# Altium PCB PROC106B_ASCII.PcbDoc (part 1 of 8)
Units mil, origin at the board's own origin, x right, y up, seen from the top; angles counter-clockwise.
Board outline 4498.18 x 1060.53 mil, 8 copper layers (Top Layer, GND1, Sig1, PWR1, PWR2, Sig2, GND2, Bottom Layer), stack 69.602 mil thick; 439 components, 327 nets, 1548 pads, 843 vias.
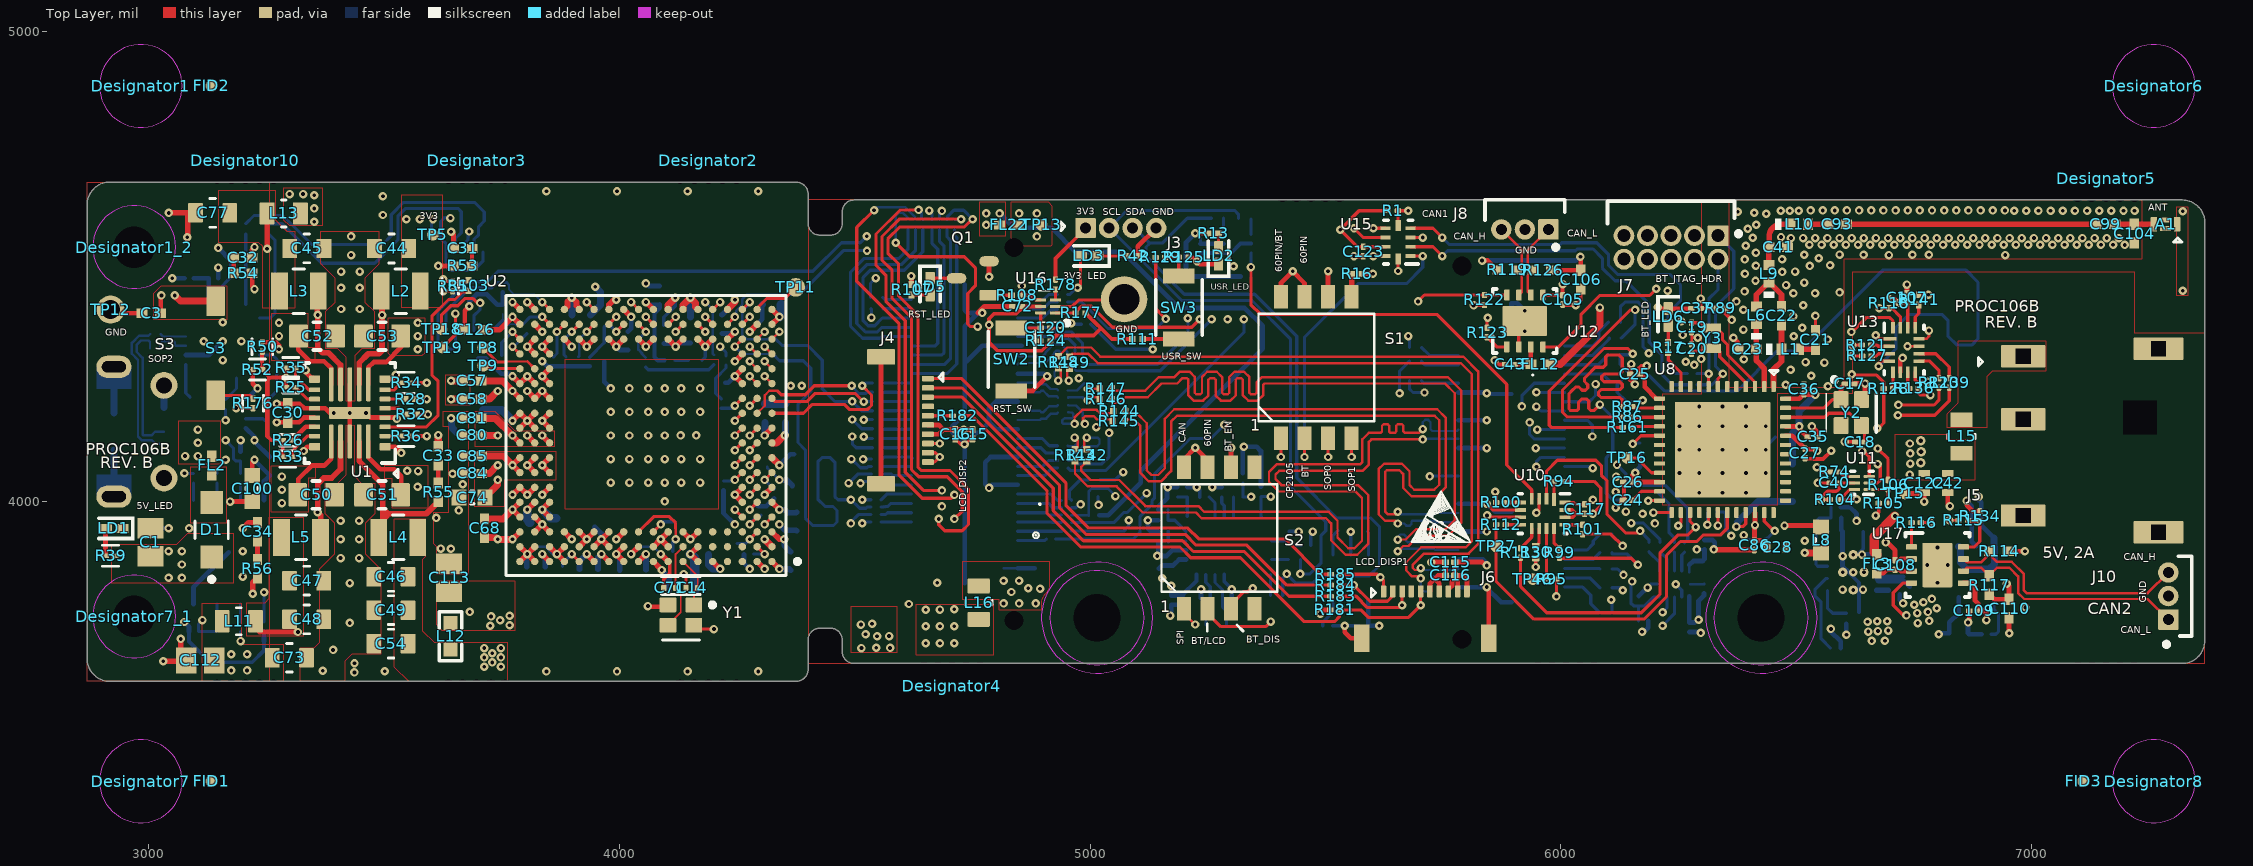
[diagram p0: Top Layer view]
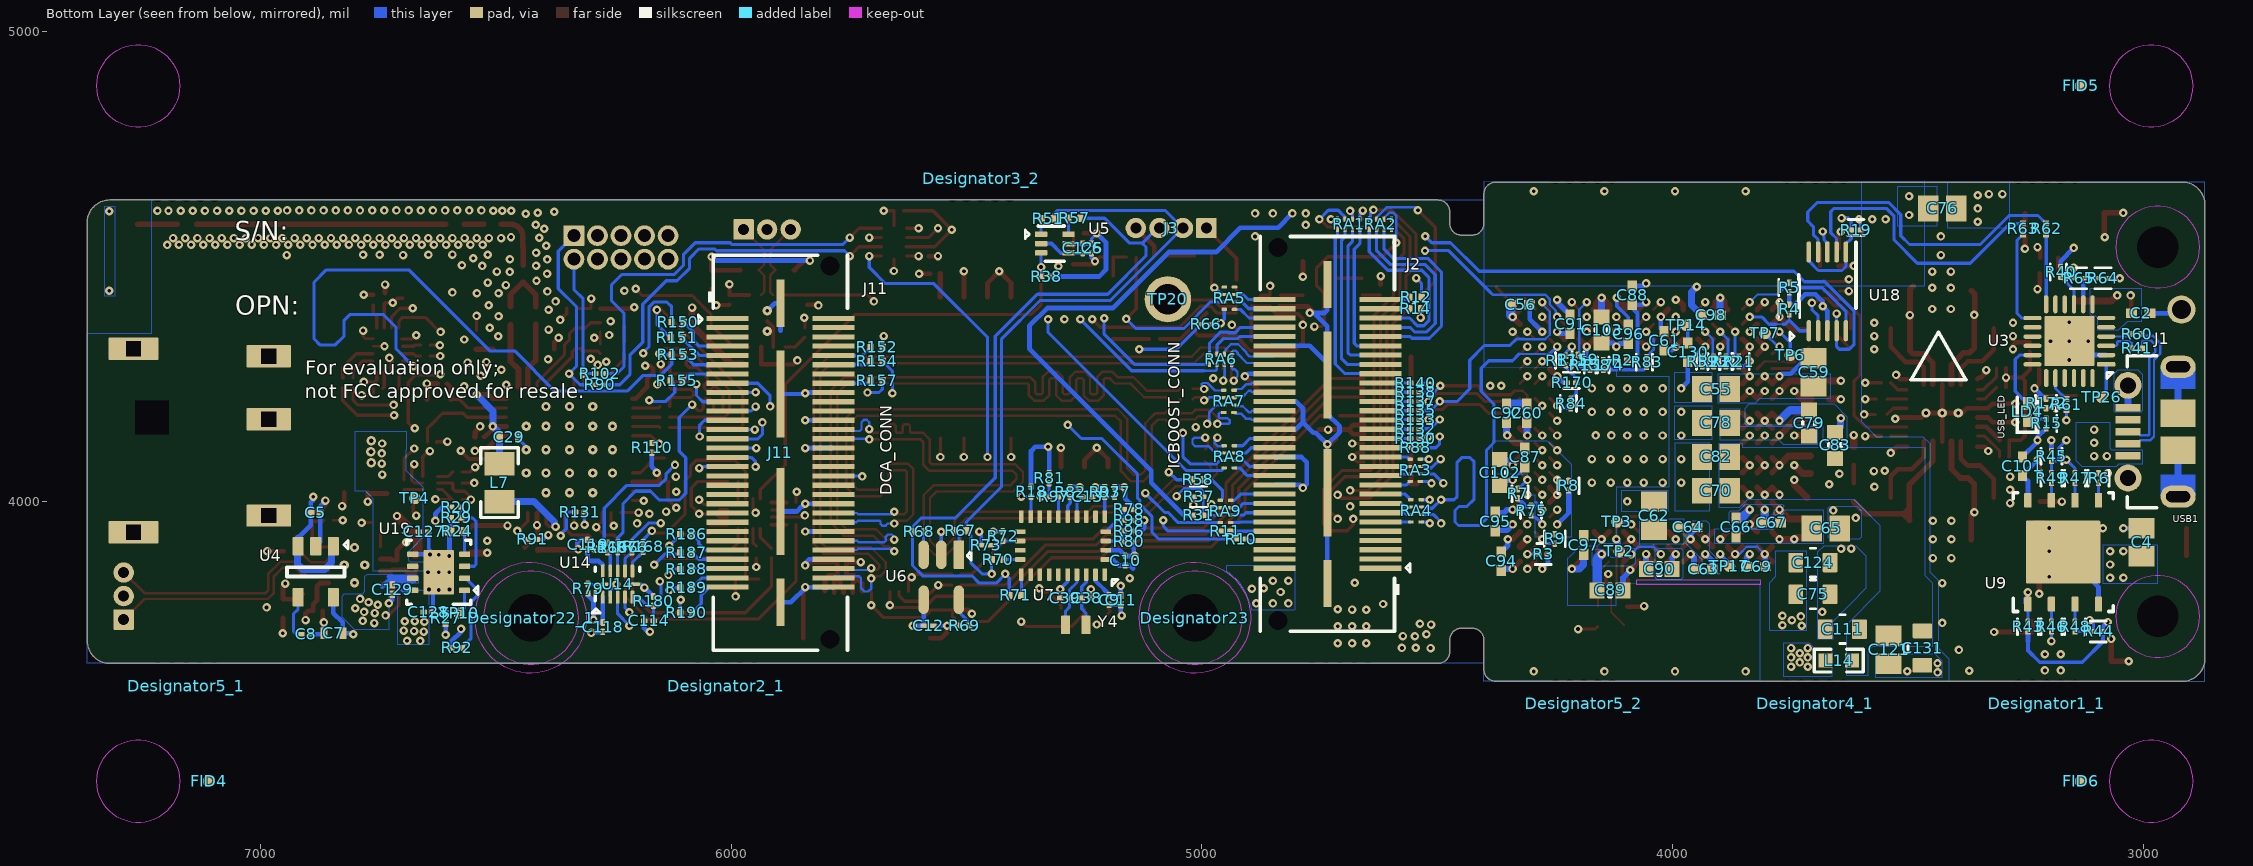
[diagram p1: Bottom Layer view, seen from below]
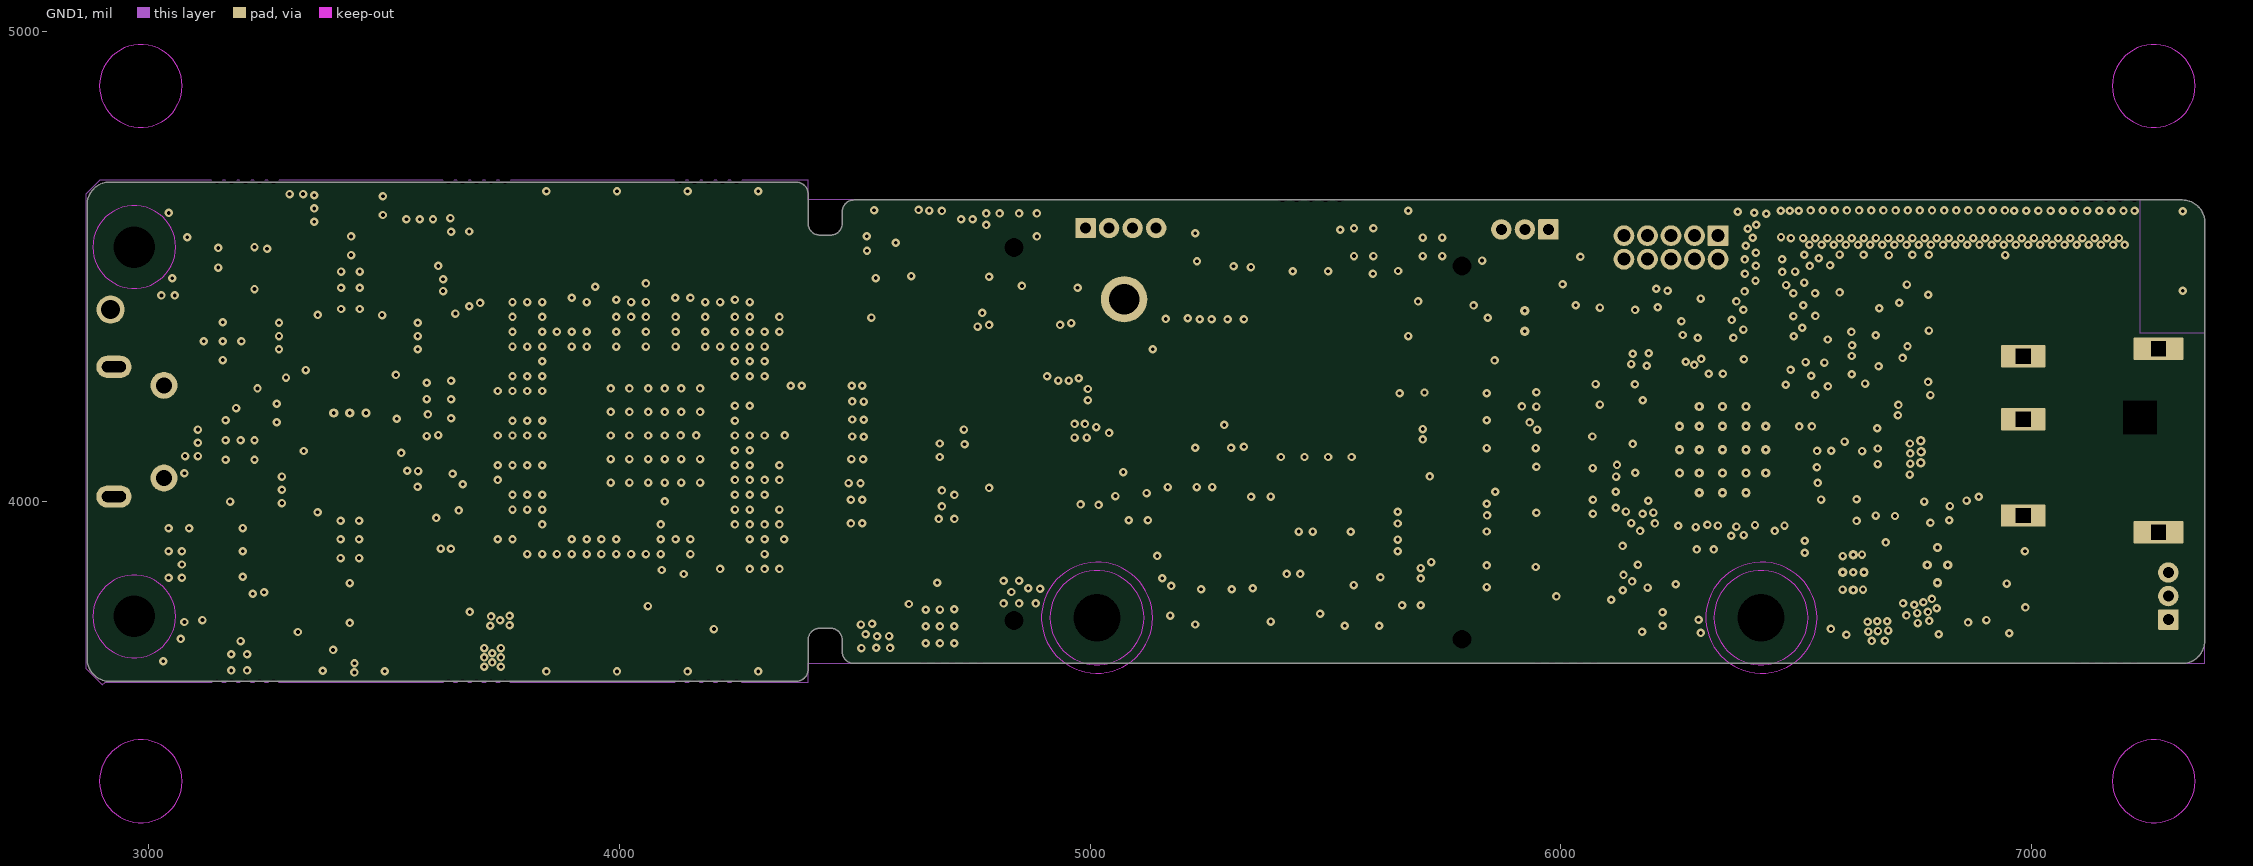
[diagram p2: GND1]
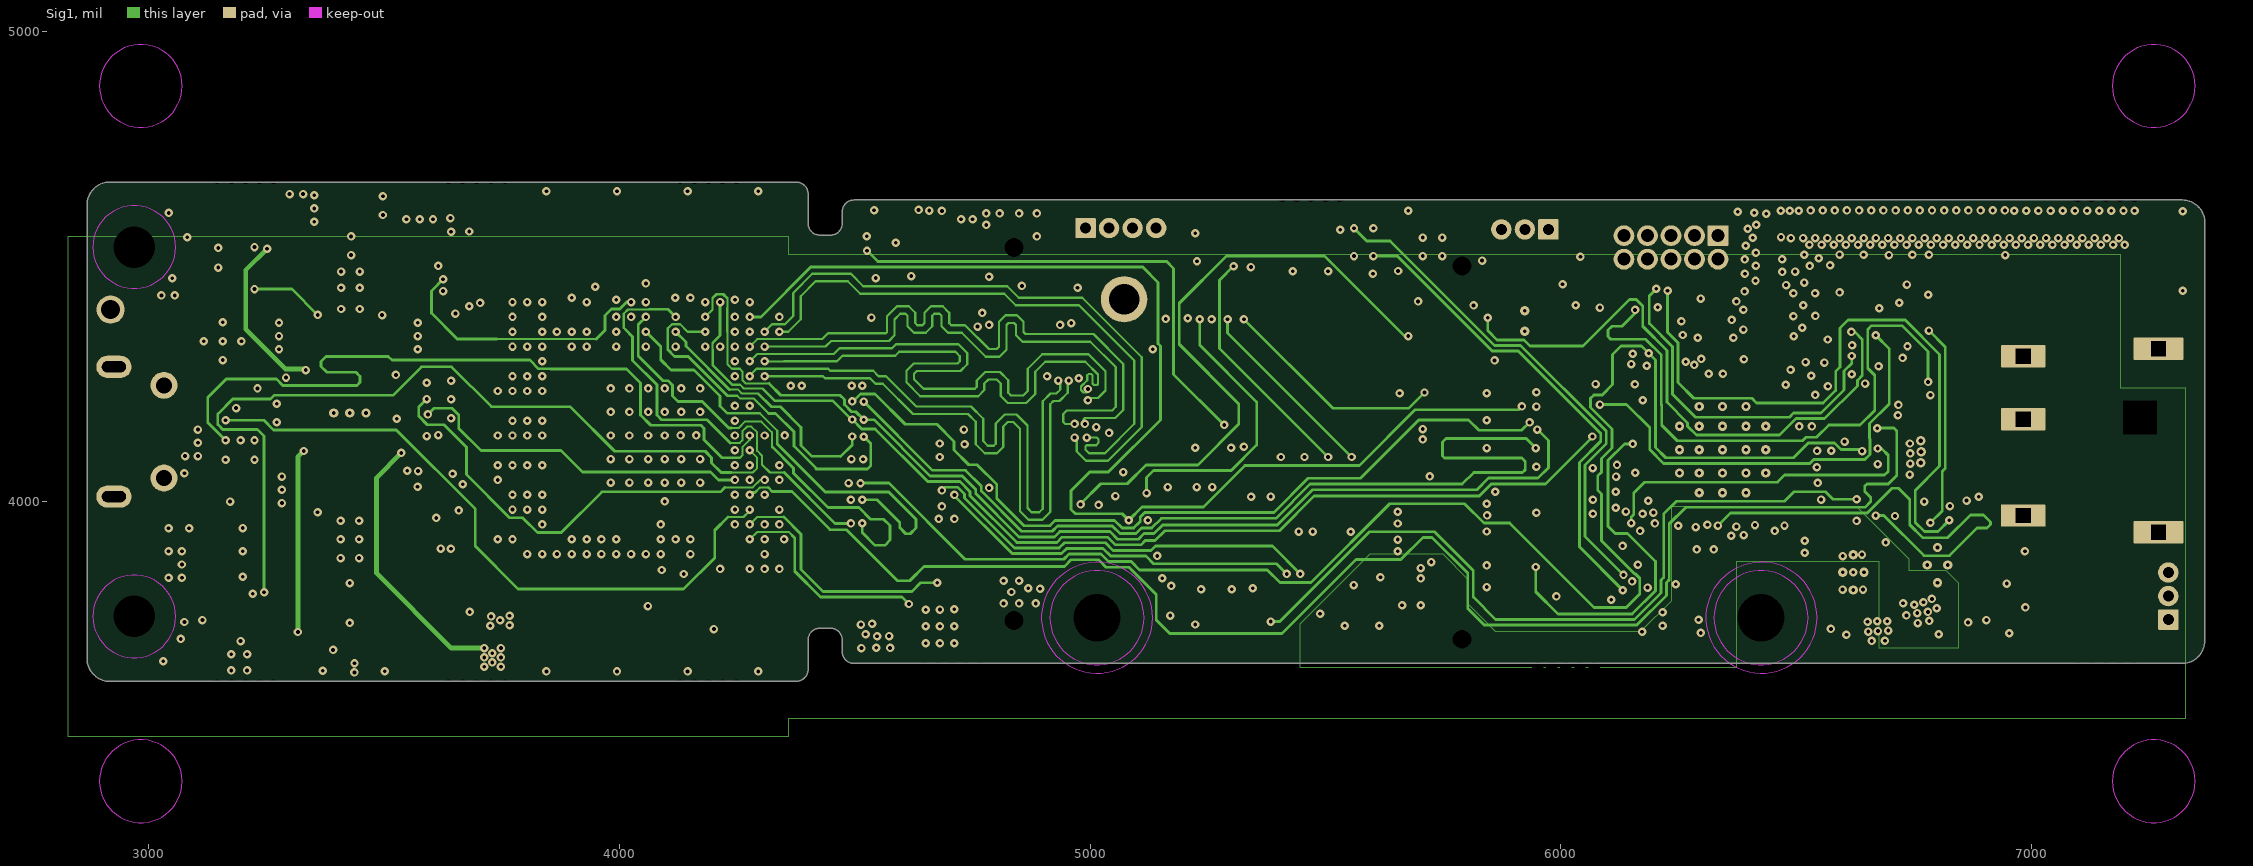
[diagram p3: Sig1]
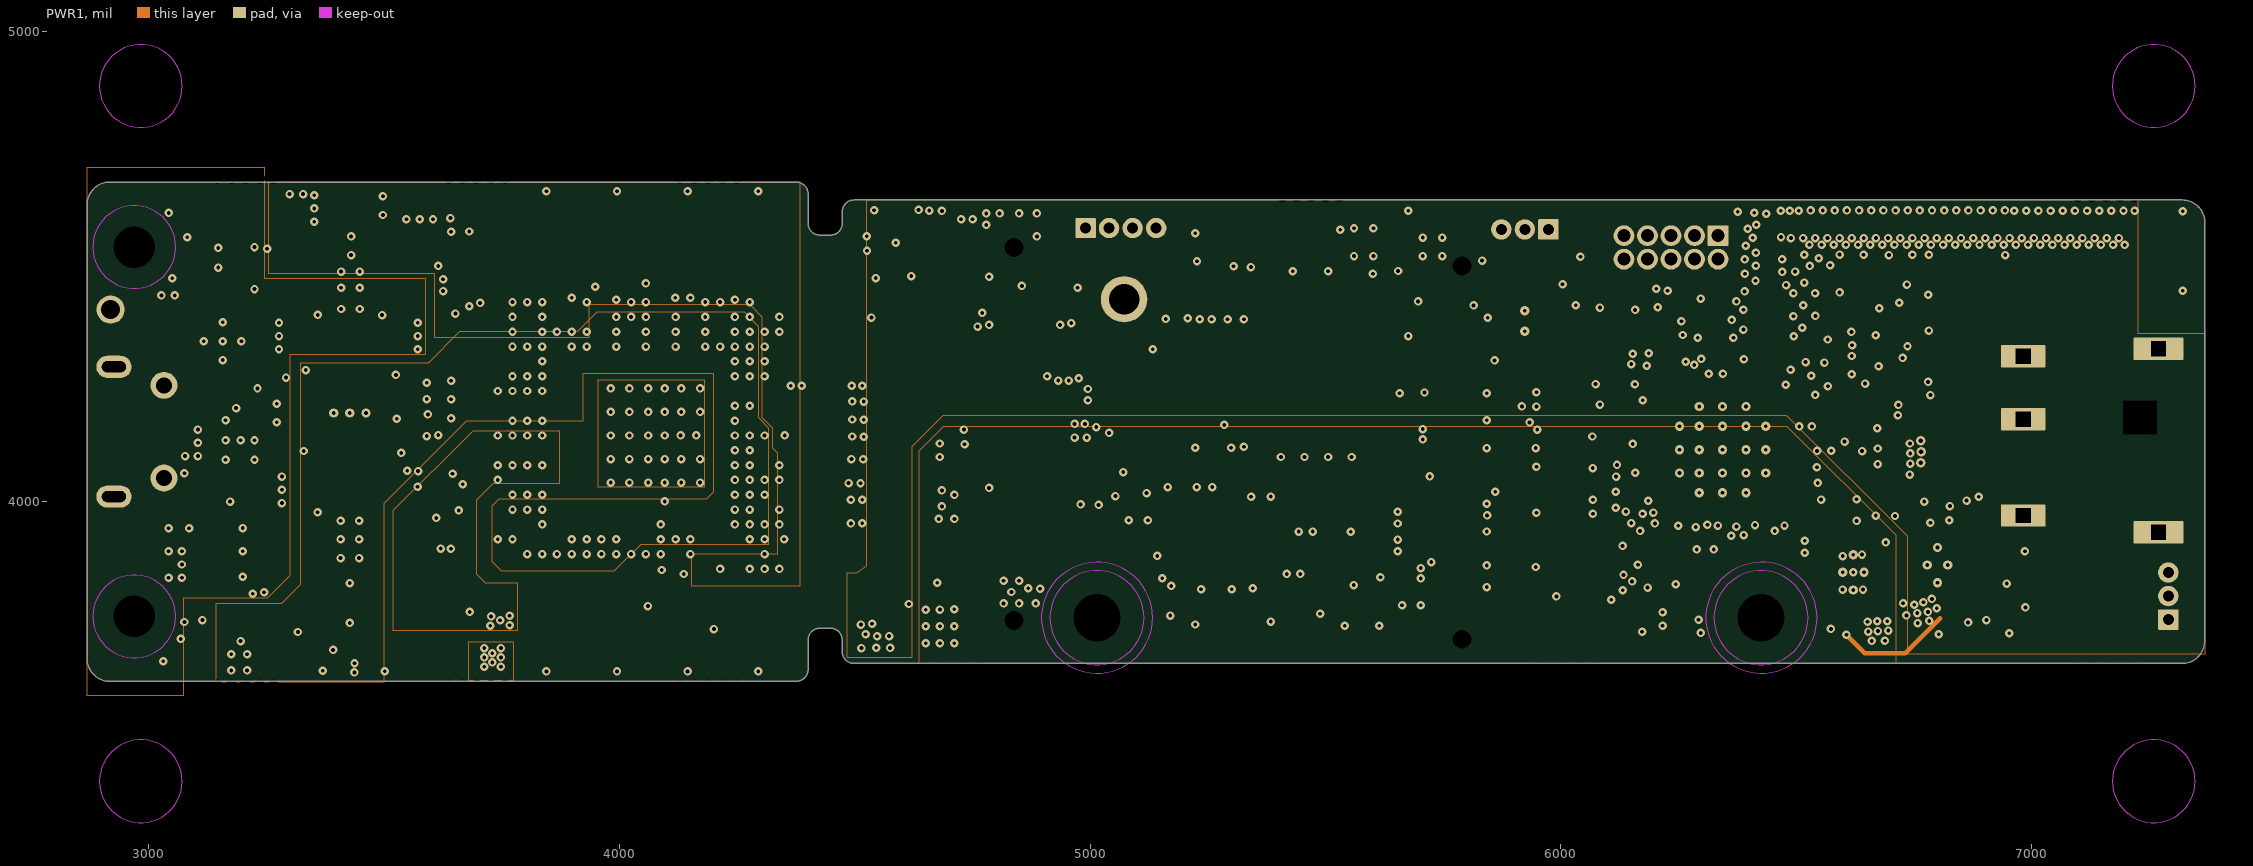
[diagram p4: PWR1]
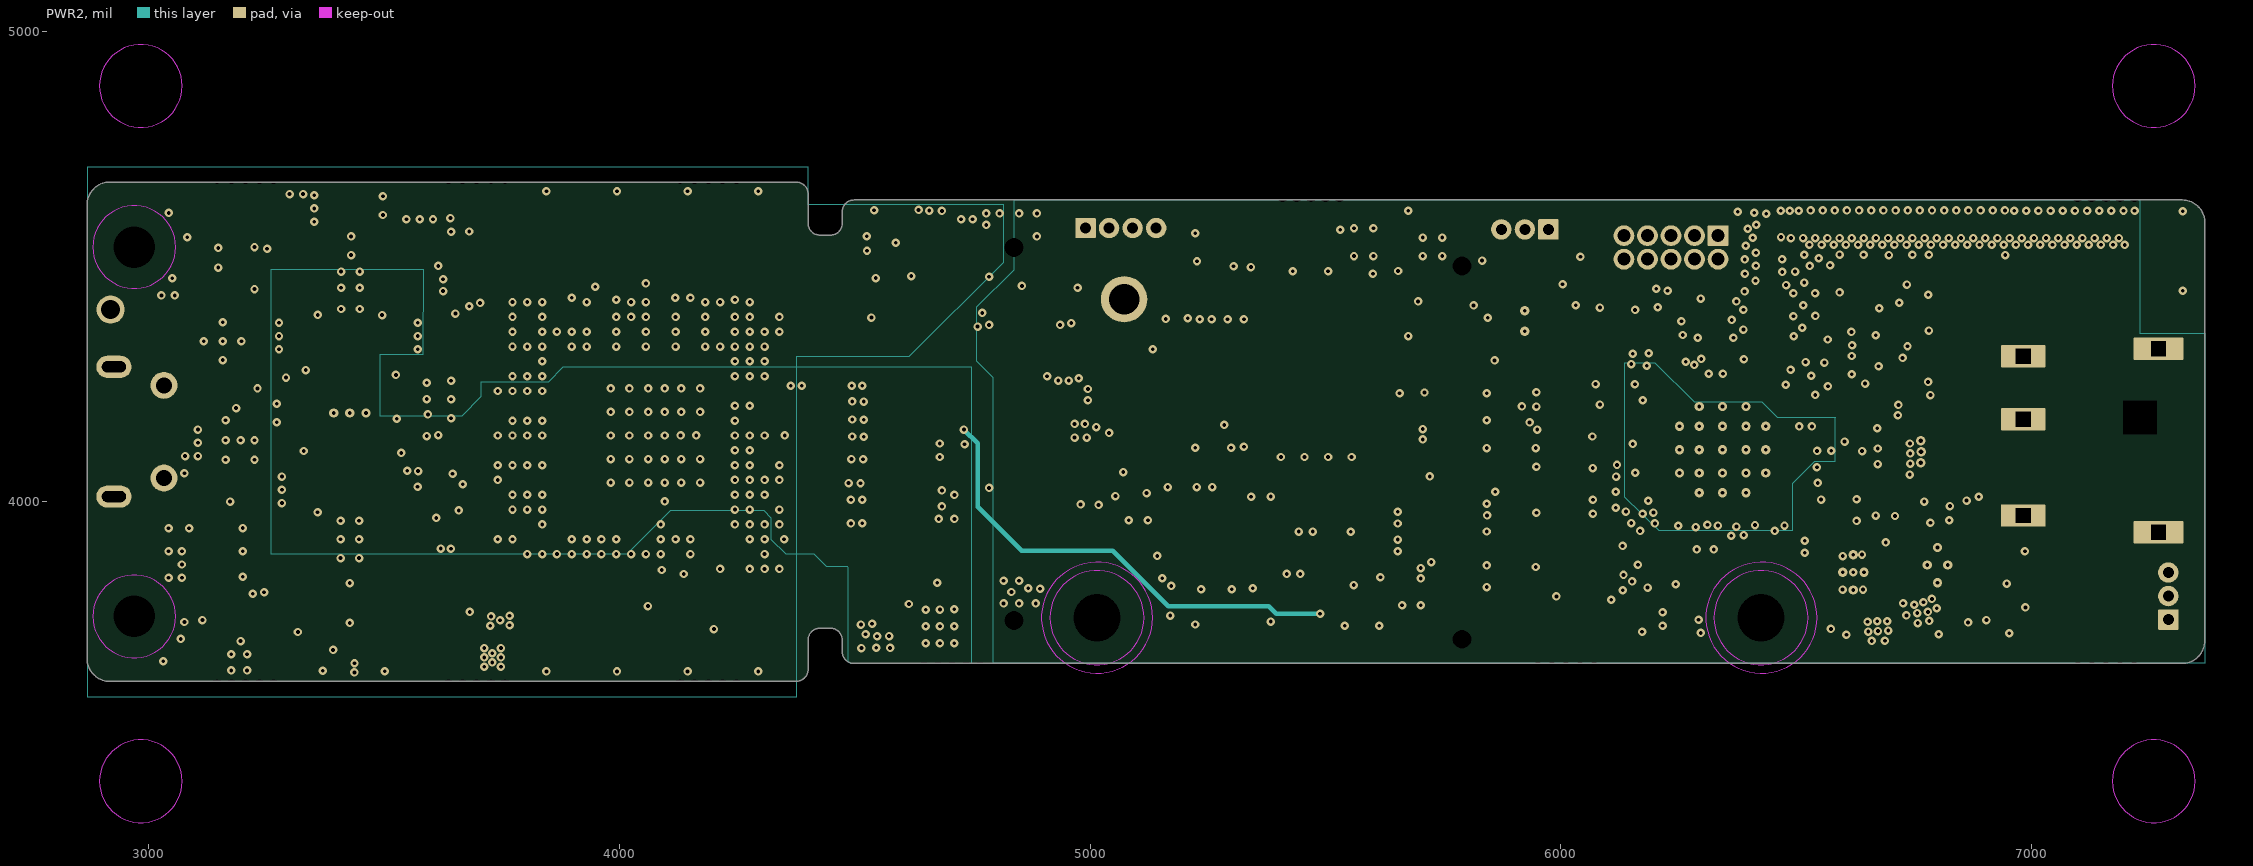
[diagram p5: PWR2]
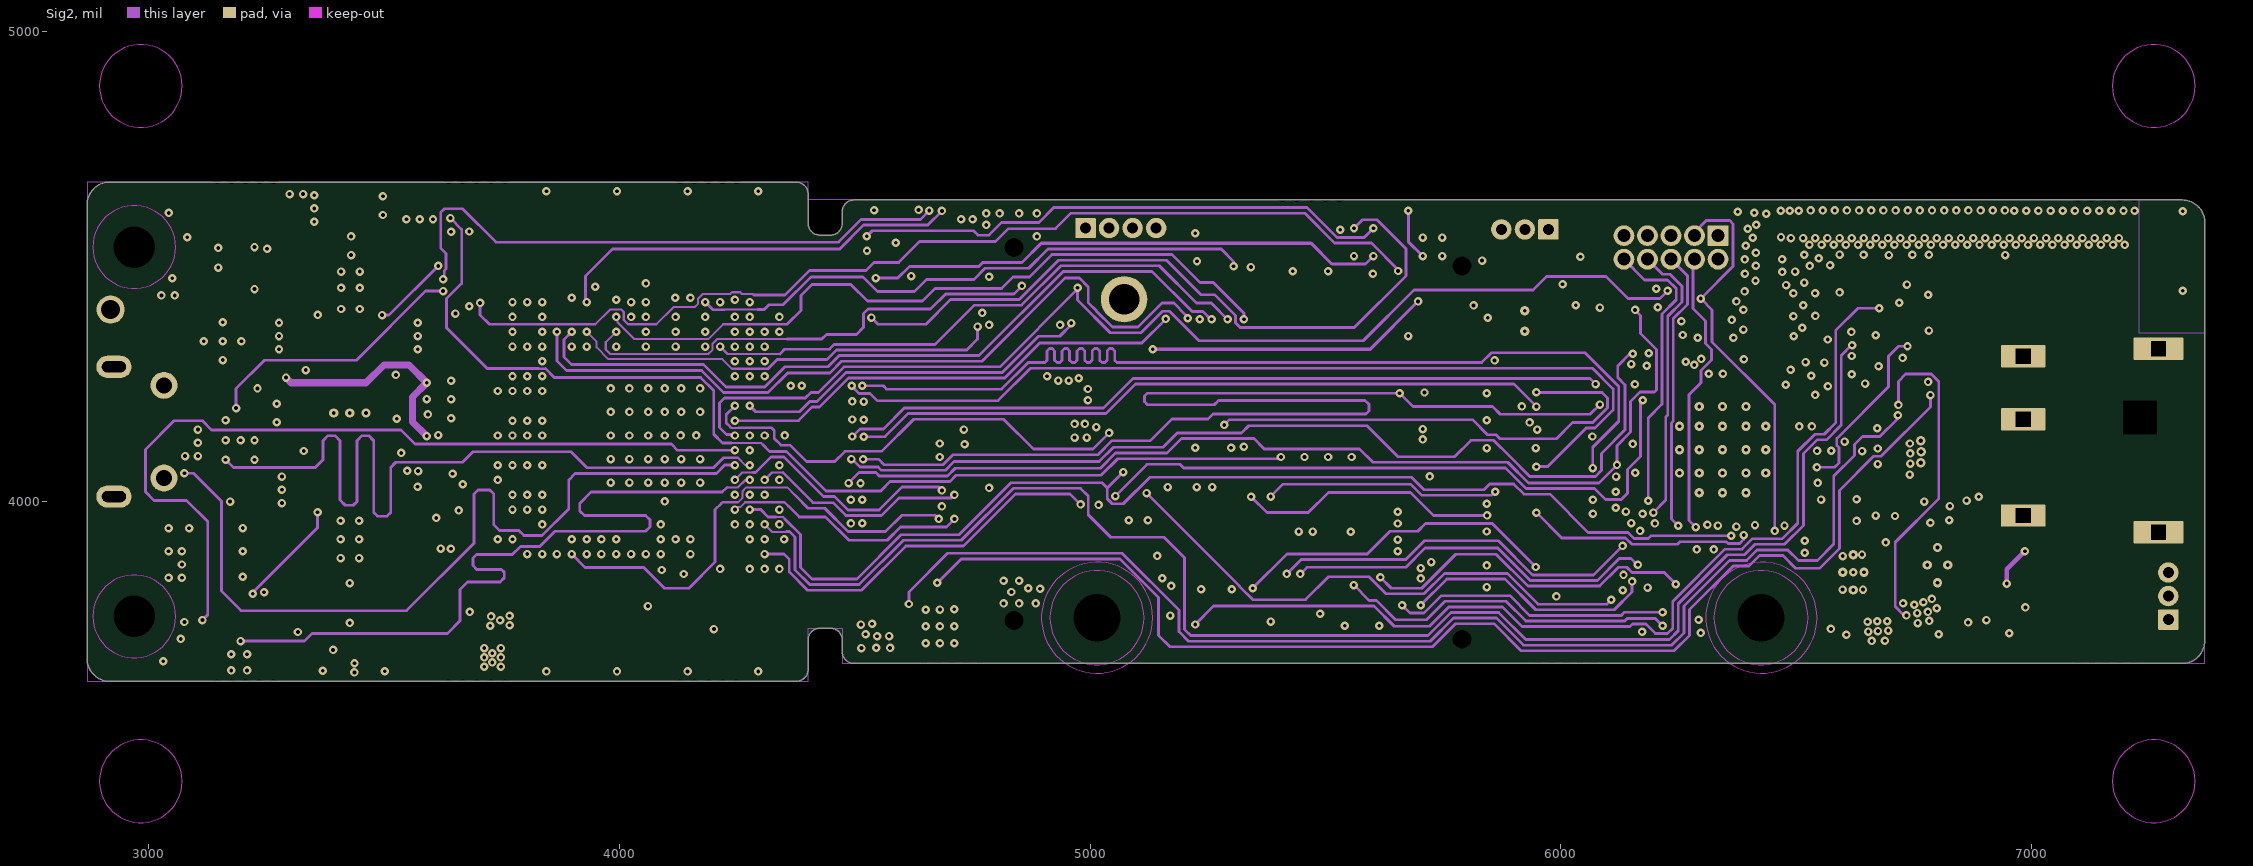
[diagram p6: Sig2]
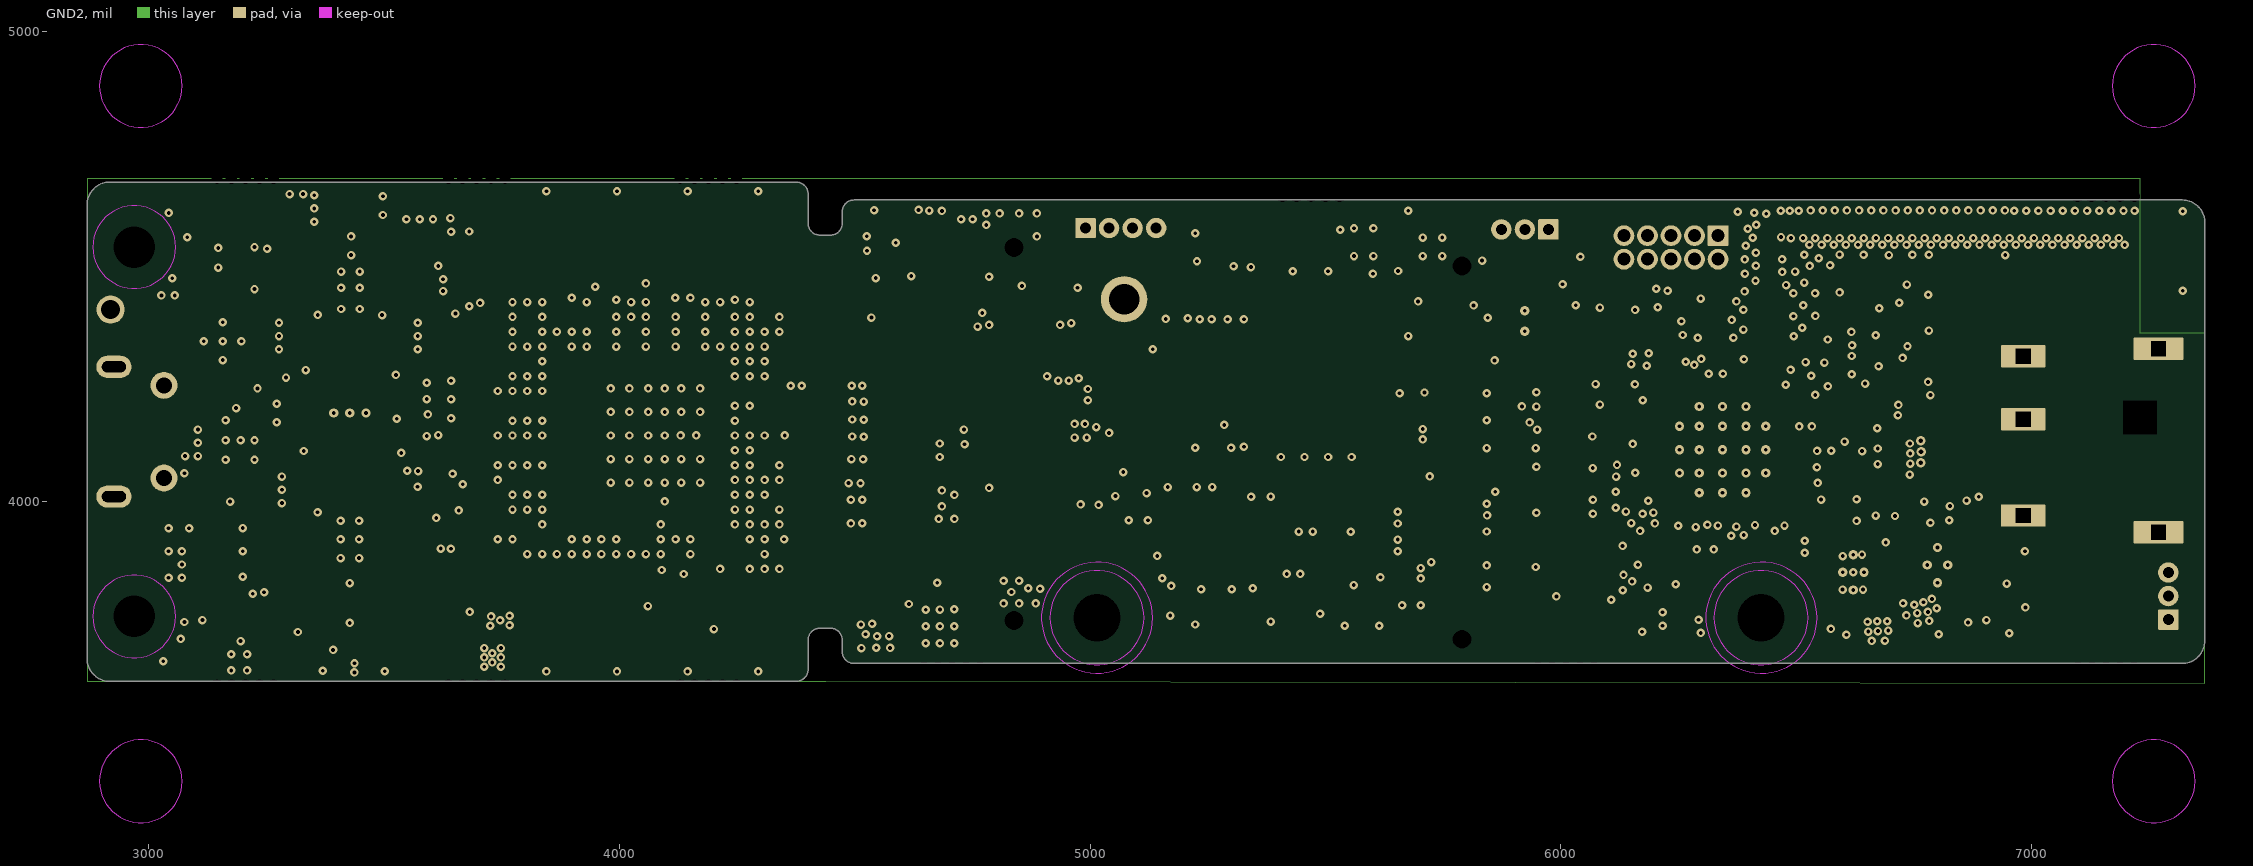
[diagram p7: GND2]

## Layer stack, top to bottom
Top Solder: solder mask 2, Solder Resist, Dk 3.9
Top Layer: signal copper 2.756
Dielectric1: prepreg 1.681, PP-006, Dk 3.79
Dielectric 1: prepreg 2.558, PP-006, Dk 3.86
GND1: signal copper 2.638
Dielectric3: core 12, Core-009, Dk 4.47
Sig1: signal copper 2.638
Dielectric2: prepreg 2.696, PP-006, Dk 4.13
Dielectric 3: prepreg 2.696, PP-006, Dk 4.13
PWR1: signal copper 2.638
Dielectric4: core 5, Core-009, Dk 4.21
PWR2: signal copper 2.638
Dielectric5: prepreg 2.696, PP-006, Dk 4.13
Dielectric 4: prepreg 2.696, PP-006, Dk 4.13
Sig2: signal copper 2.638
Dielectric8: core 12, Core-009, Dk 4.47
GND2: signal copper 2.638
Dielectric9: prepreg 2.558, PP-006, Dk 3.86
Dielectric 2: prepreg 1.681, PP-006, Dk 3.79
Bottom Layer: signal copper 2.756
Bottom Solder: solder mask 2, Solder Resist, Dk 3.9

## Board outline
2917.58,3618.9 4375.86,3618.9 4375.86,3619 ccw(c4375.86,3644) 4400.86,3644 4400.86,3706.52 cw(c4425.86,3706.52) 4425.86,3731.52 4448.63,3731.52 cw(c4448.63,3706.52) 4473.63,3706.52 4473.63,3681.91 4473.47,3681.91 ccw(c4498.47,3681.91) 4498.47,3656.91 4498.47,3656.87 7319.49,3656.87 ccw(c7319.49,3704.87) 7367.49,3704.87 7367.49,3704.83 7367.76,4593.42 7367.75,4593.44 ccw(c7319.76,4593.44) 7319.76,4641.43 4498.47,4641.43 4498.47,4641.39 ccw(c4498.47,4616.39) 4473.47,4616.39 4473.63,4591.77 cw(c4448.63,4591.77) 4448.63,4566.77 4425.86,4566.77 cw(c4425.86,4591.77) 4400.86,4591.77 4400.86,4654.3 ccw(c4375.86,4654.3) 4375.86,4679.3 4375.28,4679.43 2917.58,4679.43 ccw(c2917.58,4631.43) 2869.58,4631.43 2869.58,3666.9 ccw(c2917.58,3666.9)

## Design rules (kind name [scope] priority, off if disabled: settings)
AcuteAngle [All] p0: scope1count=1 scope1_0_kind=Board scope1_0_value=Board scope2count=1 scope2_0_kind=Board scope2_0_value=Board commentlength=0 minimum=4.50000000000000E+0001
AcuteAngle [All] p1: minimum=4.50000000000000E+0001 checktracksonly=TRUE
AssemblyTestPointUsage [All] p0: scope1count=1 scope1_0_kind=Board scope1_0_value=Board scope2count=1 scope2_0_kind=Board scope2_0_value=Board commentlength=0
AssemblyTestPointUsage [All] p1: valid=2
AssemblyTestpoint [All] p0: scope1count=1 scope1_0_kind=Board scope1_0_value=Board scope2count=1 scope2_0_kind=Board scope2_0_value=Board commentlength=0
BoardOutlineClearance [All] p0 off: scope1count=1 scope1_0_kind=Board scope1_0_value=Board scope2count=1 scope2_0_kind=Board scope2_0_value=Board commentlength=146 gap=12 // Protel DXP Scope 1 Expression Was: NOT((OnTopSilkscreen OR OnBottomSilkscreen)OR InComponentClass('FiducialMark') or InPadClass('Non Plated'))
BoardOutlineClearance BoardOutlineClearance_1 [All] p0: scope1count=1 scope1_0_kind=Net scope1_0_value=GND scope2count=1 scope2_0_kind=Board scope2_0_value=Board commentlength=0 gap=8
BoardOutlineClearance BoardOutlineClearance_1 [InNet('GND')] p1: gap=8 ignorepadtopadclearanceinfootprint=FALSE
BoardOutlineClearance [NOT((OnTopSilkscreen OR OnBottomSilkscreen)OR InComponentClass('FiducialMark') or InPadClass('Non Plated'))] p2: gap=12 ignorepadtopadclearanceinfootprint=FALSE except(0: Text-OutlineEdge)
Clearance PWR_20 [All] p0 off: scope1count=1 scope1_0_kind=Board scope1_0_value=Board scope2count=1 scope2_0_kind=NetClass scope2_0_value=PWR commentlength=56 gap=8 // Protel DXP Scope 1 Expression Was: (OnLayer('pwr2'))
Clearance 100E_1 [All] p0 off: scope1count=1 scope1_0_kind=Board scope1_0_value=Board scope2count=1 scope2_0_kind=Board scope2_0_value=Board commentlength=88 gap=8 // Protel DXP Scope 2 Expression Was: (OnLayer('Bottom Layer') or OnLayer('Top Layer'))
Clearance INNERlayer [All] p0 off: scope1count=1 scope1_0_kind=Board scope1_0_value=Board scope2count=1 scope2_0_kind=Board scope2_0_value=Board commentlength=75 gap=8 // Protel DXP Scope 1 Expression Was: (OnLayer('pwr1') or OnLayer('pwr2'))
Clearance "SAME NET" [All] p0: scope1count=1 scope1_0_kind=Board scope1_0_value=Board scope2count=1 scope2_0_kind=Board scope2_0_value=Board commentlength=0 gap=0
Clearance [All] p0: scope1count=1 scope1_0_kind=Board scope1_0_value=Board scope2count=1 scope2_0_kind=Board scope2_0_value=Board commentlength=0 gap=1
Clearance 50E_INNERlayer [All] p0 off: scope1count=1 scope1_0_kind=Board scope1_0_value=Board scope2count=1 scope2_0_kind=Board scope2_0_value=Board commentlength=75 gap=4.2 // Protel DXP Scope 1 Expression Was: (OnLayer('sig1') or OnLayer('Sig2'))
Clearance 100E [All] p0 off: scope1count=1 scope1_0_kind=Board scope1_0_value=Board scope2count=1 scope2_0_kind=Board scope2_0_value=Board commentlength=75 gap=8 // Protel DXP Scope 2 Expression Was: (OnLayer('Sig1') or OnLayer('Sig2'))
Clearance AOP_Sig [All] p0 off: scope1count=1 scope1_0_kind=Board scope1_0_value=Board scope2count=1 scope2_0_kind=Board scope2_0_value=Board commentlength=75 gap=4 // Protel DXP Scope 2 Expression Was: (OnLayer('sig1') or OnLayer('sig2'))
Clearance AOP_T-B [All] p0 off: scope1count=1 scope1_0_kind=Board scope1_0_value=Board scope2count=1 scope2_0_kind=Board scope2_0_value=Board commentlength=88 gap=4 // Protel DXP Scope 2 Expression Was: (OnLayer('Bottom Layer') or OnLayer('Top Layer'))
Clearance 90E_OUTSIDE [All] p0 off: scope1count=1 scope1_0_kind=Board scope1_0_value=Board scope2count=1 scope2_0_kind=Board scope2_0_value=Board commentlength=48 gap=6 // Protel DXP Scope 2 Expression Was: OnOutside
Clearance RF_TRACE [All] p0: scope1count=1 scope1_0_kind=NetClass scope1_0_value=RF scope2count=1 scope2_0_kind=Board scope2_0_value=Board commentlength=0 gap=4
Clearance Keepout [All] p0 off: scope1count=1 scope1_0_kind=Board scope1_0_value=Board scope2count=1 scope2_0_kind=Board scope2_0_value=Board commentlength=66 gap=0.01 // Protel DXP Scope 1 Expression Was: (OnLayer('Keep-Out Layer'))
Clearance Keepout [(OnLayer('Keep-Out Layer'))] p1: gap=0.01 ignorepadtopadclearanceinfootprint=FALSE except(5.9: THPad-THPad; 7: Arc-THPad Track-THPad THPad-Via; 8: THPad-Fill THPad-Poly THPad-Region)
Clearance RF_TRACE [InNetClass('RF')] p2: gap=4 ignorepadtopadclearanceinfootprint=FALSE except(0: Arc-Hole Track-Hole SMDPad-Hole THPad-Hole Via-Hole Fill-Hole Poly-Hole Region-Hole Text-Hole; 2: Arc-Text Track-Text SMDPad-Text THPad-Text Via-Text Fill-Text Poly-Text Region-Text Text-Text; 4.8: Track-Poly; 5: Arc-Fill Arc-Poly Arc-Region Track-Fill Track-Region; 5.9: THPad-THPad; 6: SMDPad-Fill SMDPad-Poly SMDPad-Region Via-Fill Via-Poly Via-Region; 7: Arc-THPad Track-THPad THPad-Via; 8: THPad-Fill THPad-Poly THPad-Region; 15: Fill-Fill Fill-Poly Fill-Region Poly-Poly Poly-Region Region-Region)
Clearance AOP_T-B [WithinRoom('BGA') vs (OnLayer('Bottom Layer') or OnLayer('Top Layer'))] p3: gap=4 ignorepadtopadclearanceinfootprint=TRUE except(0: Arc-Hole Track-Hole SMDPad-Hole THPad-Hole Via-Hole Fill-Hole Poly-Hole Region-Hole Text-Hole; 5.9: THPad-THPad; 7: Arc-THPad Track-THPad THPad-Via; 8: THPad-Fill THPad-Poly THPad-Region Fill-Fill Fill-Poly Fill-Region Poly-Poly Region-Region)
Clearance AOP_Sig [WithinRoom('BGA') vs (OnLayer('sig1') or OnLayer('sig2'))] p4: gap=4 ignorepadtopadclearanceinfootprint=FALSE except(0: Arc-Hole Track-Hole SMDPad-Hole THPad-Hole Via-Hole Fill-Hole Poly-Hole Region-Hole Text-Hole; 3.5: Arc-Text Track-Text SMDPad-Text THPad-Text Via-Via Via-Text Fill-Text Poly-Text Region-Text Text-Text; 3.8: SMDPad-Via; 4.5: Arc-Via Track-Via; 5.9: THPad-THPad; 7: Arc-THPad Track-THPad THPad-Via; 8: Arc-Fill Arc-Poly Arc-Region Track-Fill Track-Poly Track-Region SMDPad-THPad THPad-Fill THPad-Poly THPad-Region; 15: Fill-Fill Fill-Poly Fill-Region Poly-Poly Region-Region)
Clearance 100E [InDifferentialPairClass('100E') vs (OnLayer('Sig1') or OnLayer('Sig2'))] p5: gap=8 ignorepadtopadclearanceinfootprint=TRUE except(0: Arc-Hole Track-Hole SMDPad-Hole THPad-Hole Via-Hole Fill-Hole Poly-Hole Region-Hole Text-Hole; 2: Arc-Text Track-Text THPad-Text Via-Text Fill-Text Poly-Text Region-Text Text-Text; 4: Arc-SMDPad Track-SMDPad SMDPad-SMDPad SMDPad-THPad SMDPad-Via SMDPad-Text Via-Fill Via-Poly Via-Region; 4.5: Arc-Via Track-Via; 5.9: THPad-THPad; 6: SMDPad-Fill SMDPad-Poly SMDPad-Region Fill-Fill Fill-Poly Fill-Region Poly-Poly Poly-Region Region-Region; 7: Arc-THPad Track-THPad THPad-Via; 11: Arc-Arc Arc-Track Track-Track)
Clearance 100E_1 [InDifferentialPairClass('100E') vs (OnLayer('Bottom Layer') or OnLayer('Top Layer'))] p6: gap=8 ignorepadtopadclearanceinfootprint=FALSE except(0: Arc-Hole Track-Hole SMDPad-Hole THPad-Hole Via-Hole Fill-Hole Poly-Hole Region-Hole Text-Hole; 2: Arc-Text Track-Text THPad-Text Via-Text Fill-Text Poly-Text Region-Text Text-Text; 4: Arc-SMDPad Track-SMDPad SMDPad-SMDPad SMDPad-THPad SMDPad-Via SMDPad-Text Via-Fill Via-Poly Via-Region; 5: Arc-Via Track-Via; 5.9: THPad-THPad; 6: SMDPad-Fill SMDPad-Poly SMDPad-Region Fill-Fill Fill-Poly Fill-Region Poly-Poly Poly-Region Region-Region; 7: Arc-THPad Track-THPad THPad-Via; 10.65: Arc-Arc Arc-Track Track-Track)
Clearance 50E_INNERlayer [(OnLayer('sig1') or OnLayer('Sig2'))] p7: gap=4.2 ignorepadtopadclearanceinfootprint=TRUE except(0: Arc-Hole Track-Hole SMDPad-Hole THPad-Hole Via-Hole Fill-Hole Poly-Hole Region-Hole Text-Hole; 2: SMDPad-Text Fill-Text Poly-Text Region-Text Text-Text; 4: Via-Fill Via-Poly Via-Region Poly-Region; 4.35: Arc-Via Track-Via; 5.9: THPad-THPad; 5.95: Arc-Arc Arc-Track Track-Track; 6: SMDPad-Fill SMDPad-Poly SMDPad-Region; 7: Arc-THPad Track-THPad THPad-Via; 8: Arc-Fill Arc-Poly Arc-Region Track-Fill Track-Poly Track-Region THPad-Fill THPad-Poly THPad-Region; 12: Fill-Fill Fill-Poly Fill-Region Poly-Poly Region-Region)
Clearance PWR_20 [(OnLayer('pwr2')) vs InNetClass('PWR')] p8: gap=8 ignorepadtopadclearanceinfootprint=TRUE except(0: Arc-Hole Track-Hole SMDPad-Hole THPad-Hole Via-Hole Fill-Hole Poly-Hole Region-Hole Text-Hole; 2: SMDPad-Text Fill-Text Poly-Text Region-Text Text-Text; 4.2: Arc-Text Track-Text THPad-Text Via-Via Via-Text; 5: THPad-Fill THPad-Poly THPad-Region; 5.9: THPad-THPad; 6: Arc-Via Arc-Fill Arc-Poly Arc-Region Track-Via Track-Fill Track-Poly Track-Region; 7: THPad-Via; 10: Via-Fill Via-Poly Via-Region; 20: Fill-Fill Fill-Poly Fill-Region Poly-Poly Poly-Region Region-Region)
Clearance INNERlayer [(OnLayer('pwr1') or OnLayer('pwr2'))] p9: gap=8 ignorepadtopadclearanceinfootprint=TRUE except(0: Arc-Hole Track-Hole SMDPad-Hole THPad-Hole Via-Hole Fill-Hole Poly-Hole Region-Hole Text-Hole; 2: SMDPad-Text Fill-Text Poly-Text Region-Text Text-Text; 4: Via-Fill Via-Poly Via-Region; 4.2: Arc-Text Track-Text THPad-Text Via-Via Via-Text; 5: THPad-Fill THPad-Poly THPad-Region; 5.9: THPad-THPad; 6: Arc-Via Arc-Fill Arc-Poly Arc-Region Track-Via Track-Fill Track-Poly Track-Region; 7: THPad-Via; 20: Fill-Fill Fill-Poly Fill-Region Poly-Poly Poly-Region Region-Region)
Clearance 90E_OUTSIDE [InDifferentialPairClass('90E') vs OnOutside] p10: gap=6 ignorepadtopadclearanceinfootprint=TRUE except(0: Arc-Hole Track-Hole SMDPad-Hole THPad-Hole Via-Hole Fill-Fill Fill-Poly Fill-Region Fill-Hole Poly-Poly Poly-Region Poly-Hole Region-Region Region-Hole Text-Hole; 2: Arc-Text Track-Text SMDPad-Text THPad-Text Via-Text Fill-Text Poly-Text Region-Text Text-Text; 4: Arc-SMDPad Track-SMDPad SMDPad-SMDPad Via-Via Via-Fill Via-Poly Via-Region; 4.5: Arc-Arc Arc-Track Arc-Via Track-Track Track-Via; 5.9: THPad-THPad; 7: Arc-THPad Track-THPad SMDPad-THPad THPad-Via; 8: SMDPad-Via THPad-Fill THPad-Poly THPad-Region)
Clearance [All] p11: gap=1 ignorepadtopadclearanceinfootprint=TRUE except(0: Arc-Hole Track-Hole SMDPad-Hole THPad-Hole Via-Hole Fill-Hole Poly-Hole Region-Hole Text-Hole; 4: Arc-SMDPad Track-SMDPad SMDPad-SMDPad SMDPad-Via Via-Via Via-Fill Via-Poly Via-Region Poly-Region; 4.2: Arc-Via Track-Via; 5: Arc-Fill Arc-Poly Arc-Region Track-Fill Track-Poly Track-Region; 5.85: Arc-Arc Arc-Track Track-Track; 5.9: THPad-THPad; 6: SMDPad-Fill SMDPad-Poly SMDPad-Region; 7: Arc-THPad Track-THPad SMDPad-THPad THPad-Via; 8: THPad-Fill THPad-Poly THPad-Region; 12: Fill-Fill Fill-Poly Fill-Region Poly-Poly Region-Region)
Clearance "SAME NET" [All] p12: gap=0 ignorepadtopadclearanceinfootprint=FALSE except(0.5: SMDPad-Text; 5.9: THPad-THPad)
ComponentClearance ComponentClearance_THtoTH [All] p0 off: scope1count=1 scope1_0_kind=Board scope1_0_value=Board scope2count=1 scope2_0_kind=Board scope2_0_value=Board commentlength=54 gap=20 collisioncheckmode=3 // Protel DXP Scope 2 Expression Was: IsThruComponent
ComponentClearance ComponentClearance_THtoSMT [All] p0 off: scope1count=1 scope1_0_kind=Board scope1_0_value=Board scope2count=1 scope2_0_kind=Board scope2_0_value=Board commentlength=53 gap=5 collisioncheckmode=3 // Protel DXP Scope 2 Expression Was: IsSMTComponent
ComponentClearance ComponentClearance_SmallPassives [All] p0 off: scope1count=1 scope1_0_kind=Board scope1_0_value=Board scope2count=1 scope2_0_kind=Board scope2_0_value=Board commentlength=508 gap=10 collisioncheckmode=3 // Protel DXP Scope 2 Expression Was: HasFootprint('0201*') or HasFootprint('0402*') or HasFootprint('0508') or HasFootprint('0603*') or HasFootprint('0612') or HasFootprint('0805*') or HasFootprint('0815*') or HasFootprint('0830*') or HasFootprint('1206*') or HasFootprint('1210*') or HasFootprint('1808*') or HasFootprint('1812*') or HasFootprint('1825*') or HasFootprint('2010*') or HasFootprint('2220*') or HasFootprint('2225*') or HasFootprint('2512*') or HasFootprint('2728*') or HasFootprint('3518*')
ComponentClearance ComponentClearance_MountingHoles [All] p0: scope1count=1 scope1_0_kind=ComponentClass scope1_0_value="Mounting Holes" scope2count=1 scope2_0_kind=Board scope2_0_value=Board commentlength=0 gap=20 collisioncheckmode=3
ComponentClearance ComponentClearance_ScrewToNut [All] p0 off: scope1count=1 scope1_0_kind=Board scope1_0_value=Board scope2count=1 scope2_0_kind=Board scope2_0_value=Board commentlength=71 gap=5 collisioncheckmode=3 // Protel DXP Scope 2 Expression Was: (HasFootprint('Keystone_1902C'))
ComponentClearance ComponentClearance_Logo [All] p0: scope1count=1 scope1_0_kind=ComponentClass scope1_0_value=Logo scope2count=1 scope2_0_kind=Board scope2_0_value=Board commentlength=0 gap=50 collisioncheckmode=3
ComponentClearance ComponentClearance_Shunt [All] p0: scope1count=1 scope1_0_kind=ComponentClass scope1_0_value=Header scope2count=1 scope2_0_kind=ComponentClass scope2_0_value=Shunt commentlength=0 gap=1 collisioncheckmode=3
ComponentClearance ComponentClearance_MountingHoles_FiducialMarks [All] p0: scope1count=1 scope1_0_kind=ComponentClass scope1_0_value="Mounting Holes" scope2count=1 scope2_0_kind=ComponentClass scope2_0_value=FiducialMark commentlength=0 gap=50 collisioncheckmode=3
ComponentClearance [All] p0: scope1count=1 scope1_0_kind=Board scope1_0_value=Board scope2count=1 scope2_0_kind=Board scope2_0_value=Board commentlength=0 gap=1 collisioncheckmode=3
ComponentClearance ComponentClearance_R188_204 [All] p0: scope1count=1 scope1_0_kind=Component scope1_0_value=R188 scope2count=1 scope2_0_kind=Component scope2_0_value=R204 commentlength=0 gap=-1 collisioncheckmode=3
ComponentClearance ComponentClearance_R199_187 [All] p0 off: scope1count=1 scope1_0_kind=Board scope1_0_value=Board scope2count=1 scope2_0_kind=Board scope2_0_value=Board commentlength=80 gap=-1 collisioncheckmode=3 // Protel DXP Scope 1 Expression Was: InComponent('J11') or InComponent('TP20')
ComponentClearance ComponentClearance_R199_187 [InComponent('J11') or InComponent('TP20')] p1: gap=-1 collisioncheckmode=3 verticalgap=10 showdistances=FALSE
ComponentClearance ComponentClearance_R188_204 [InComponent('R188') vs InComponent('R204')] p2: gap=-1 collisioncheckmode=3 verticalgap=10 showdistances=FALSE
ComponentClearance [All] p3: gap=1 collisioncheckmode=3 verticalgap=10 showdistances=FALSE
ComponentClearance ComponentClearance_MountingHoles_FiducialMarks [InComponentClass('Mounting Holes') vs InComponentClass('FiducialMark')] p4: gap=50 collisioncheckmode=3 verticalgap=10 showdistances=FALSE
ComponentClearance ComponentClearance_Shunt [InComponentClass('Header') vs InComponentClass('Shunt')] p5: gap=1 collisioncheckmode=3 verticalgap=0 showdistances=FALSE
ComponentClearance ComponentClearance_Logo [InComponentClass('Logo')] p6: gap=50 collisioncheckmode=3 verticalgap=10 showdistances=FALSE
ComponentClearance ComponentClearance_ScrewToNut [(HasFootprint('NY PMS 440 0025 PH')) vs (HasFootprint('Keystone_1902C'))] p7: gap=5 collisioncheckmode=3 verticalgap=10 showdistances=FALSE
ComponentClearance ComponentClearance_MountingHoles [InComponentClass('Mounting Holes')] p8: gap=20 collisioncheckmode=3 verticalgap=100000 showdistances=FALSE
ComponentClearance ComponentClearance_SmallPassives [HasFootprint('0201*') or HasFootprint('0402*') or HasFootprint('0508') or HasFootprint('0603*') or HasFootprint('0612') or HasFootprint('0805*') or HasFootprint('0815*') or HasFootprint('0830*') or HasFootprint('1206*') or HasFootprint('1210*') or HasFootprint('1808*') or HasFootprint('1812*') or HasFootprint('1825*') or HasFootprint('2010*') or HasFootprint('2220*') or HasFootprint('2225*') or HasFootprint('2512*') or HasFootprint('2728*') or HasFootprint('3518*') vs HasFootprint('0201*') or HasFootprint('0402*') or HasFootprint('0508') or HasFootprint('0603*') or HasFootprint('0612') or HasFootprint('0805*') or HasFootprint('0815*') or HasFootprint('0830*') or HasFootprint('1206*') or HasFootprint('1210*') or HasFootprint('1808*') or HasFootprint('1812*') or HasFootprint('1825*') or HasFootprint('2010*') or HasFootprint('2220*') or HasFootprint('2225*') or HasFootprint('2512*') or HasFootprint('2728*') or HasFootprint('3518*')] p9: gap=10 collisioncheckmode=3 verticalgap=10 showdistances=FALSE
ComponentClearance ComponentClearance_THtoSMT [IsThruComponent vs IsSMTComponent] p10: gap=5 collisioncheckmode=3 verticalgap=20 showdistances=FALSE
ComponentClearance ComponentClearance_THtoTH [IsThruComponent vs IsThruComponent] p11: gap=20 collisioncheckmode=3 verticalgap=30 showdistances=FALSE
DiffPairsRouting Diff_120E [All] p0 off: scope1count=1 scope1_0_kind=Board scope1_0_value=Board scope2count=1 scope2_0_kind=Board scope2_0_value=Board commentlength=70 // Protel DXP Scope 1 Expression Was: InDifferentialPairClass('120E')
DiffPairsRouting Diff_100E [All] p0 off: scope1count=1 scope1_0_kind=Board scope1_0_value=Board scope2count=1 scope2_0_kind=Board scope2_0_value=Board commentlength=70 // Protel DXP Scope 1 Expression Was: InDifferentialPairClass('100E')
DiffPairsRouting Diff_90E [All] p0 off: scope1count=1 scope1_0_kind=Board scope1_0_value=Board scope2count=1 scope2_0_kind=Board scope2_0_value=Board commentlength=69 // Protel DXP Scope 1 Expression Was: InDifferentialPairClass('90E')
DiffPairsRouting Diff_100E [InDifferentialPairClass('100E')] p1: maxlimit=11.2 minlimit=8.6 mostfreqgap=10 toplayer_maxgap=8.6 toplayer_prefgap=8.6 toplayer_minwidth=5.1 toplayer_maxwidth=5.1 toplayer_prefwidth=5.1 midlayer1_mingap=10 midlayer1_maxgap=10 midlayer1_minwidth=15 midlayer1_maxwidth=15 midlayer1_prefwidth=15 midlayer2_mingap=11.2 midlayer2_prefgap=11.2 midlayer2_minwidth=4.5 midlayer2_maxwidth=4.8 midlayer2_prefwidth=4.8 midlayer3_mingap=10 midlayer3_maxgap=10 midlayer3_minwidth=15 midlayer3_maxwidth=15 midlayer3_prefwidth=15 midlayer6_mingap=10 midlayer6_maxgap=10 midlayer6_minwidth=15 midlayer6_maxwidth=15 midlayer6_prefwidth=15 midlayer7_mingap=11.2 midlayer7_prefgap=11.2 midlayer7_minwidth=4.5 midlayer7_maxwidth=4.8 midlayer7_prefwidth=4.8 midlayer8_mingap=10 midlayer8_maxgap=10 midlayer8_minwidth=15 midlayer8_maxwidth=15 midlayer8_prefwidth=15 bottomlayer_maxgap=8.6 bottomlayer_prefgap=8.6 bottomlayer_minwidth=5.1 bottomlayer_maxwidth=5.1 bottomlayer_prefwidth=5.1 maxuncoupledlength=500
DiffPairsRouting Diff_90E [InDifferentialPairClass('90E')] p2: maxlimit=100 minlimit=5 mostfreqgap=10 toplayer_maxgap=5 toplayer_prefgap=5 toplayer_minwidth=5 toplayer_maxwidth=5 toplayer_prefwidth=5 midlayer1_mingap=10 midlayer1_minwidth=15 midlayer1_maxwidth=15 midlayer1_prefwidth=15 midlayer2_mingap=7.4 midlayer2_maxgap=7.4 midlayer2_prefgap=7.4 midlayer2_minwidth=5 midlayer2_maxwidth=5 midlayer2_prefwidth=5 midlayer3_mingap=10 midlayer3_minwidth=15 midlayer3_maxwidth=15 midlayer3_prefwidth=15 midlayer6_mingap=10 midlayer6_minwidth=15 midlayer6_maxwidth=15 midlayer6_prefwidth=15 midlayer7_mingap=7.4 midlayer7_maxgap=7.4 midlayer7_prefgap=7.4 midlayer7_minwidth=5 midlayer7_maxwidth=5 midlayer7_prefwidth=5 midlayer8_mingap=10 midlayer8_minwidth=15 midlayer8_maxwidth=15 midlayer8_prefwidth=15 bottomlayer_maxgap=5 bottomlayer_prefgap=5 bottomlayer_minwidth=5 bottomlayer_maxwidth=5 bottomlayer_prefwidth=5 maxuncoupledlength=1000
DiffPairsRouting Diff_120E [InDifferentialPairClass('120E')] p3: maxlimit=10 minlimit=6.1 mostfreqgap=10 toplayer_mingap=7.15 toplayer_maxgap=7.15 toplayer_prefgap=7.15 toplayer_minwidth=5.2 toplayer_maxwidth=5.2 toplayer_prefwidth=5.2 midlayer1_mingap=10 midlayer1_minwidth=15 midlayer1_maxwidth=15 midlayer1_prefwidth=15 midlayer2_mingap=10 midlayer2_minwidth=15 midlayer2_maxwidth=15 midlayer2_prefwidth=15 midlayer3_mingap=10 midlayer3_minwidth=15 midlayer3_maxwidth=15 midlayer3_prefwidth=15 midlayer6_mingap=10 midlayer6_minwidth=15 midlayer6_maxwidth=15 midlayer6_prefwidth=15 midlayer7_mingap=10 midlayer7_minwidth=15 midlayer7_maxwidth=15 midlayer7_prefwidth=15 midlayer8_mingap=10 midlayer8_minwidth=15 midlayer8_maxwidth=15 midlayer8_prefwidth=15 bottomlayer_maxgap=6.1 bottomlayer_prefgap=6.1 bottomlayer_minwidth=4 bottomlayer_maxwidth=4 bottomlayer_prefwidth=4 maxuncoupledlength=500
FabricationTestPointUsage TestPointUsage [All] p0: scope1count=1 scope1_0_kind=Board scope1_0_value=Board scope2count=1 scope2_0_kind=Board scope2_0_value=Board commentlength=0 valid=2 allowmultiple=FALSE
FabricationTestPointUsage TestPointUsage [All] p1: valid=2 allowmultiple=FALSE
FabricationTestpoint Testpoint [All] p0: scope1count=1 scope1_0_kind=Board scope1_0_value=Board scope2count=1 scope2_0_kind=Board scope2_0_value=Board commentlength=0 side=3 testpointundercomponent=TRUE minsize=40 maxsize=100 preferedsize=60 minholesize=0 maxholesize=40 preferedholesize=32 testpointgrid=1
FabricationTestpoint Testpoint [All] p1: side=3 testpointundercomponent=TRUE minsize=40 maxsize=100 preferedsize=60 minholesize=0 maxholesize=40 preferedholesize=32 testpointgrid=1 allowsidetop=TRUE allowsidebottom=TRUE usegrid=TRUE gridtolerance=0.01
FanoutControl Fanout_Small [All] p0 off: scope1count=1 scope1_0_kind=Board scope1_0_value=Board scope2count=1 scope2_0_kind=Board scope2_0_value=Board commentlength=84 // Protel DXP Scope 1 Expression Was: (CompPinCount < 5)   Fanout_Small (Default Rule)
FanoutControl Fanout_Default [All] p0: scope1count=1 scope1_0_kind=Board scope1_0_value=Board scope2count=1 scope2_0_kind=Board scope2_0_value=Board commentlength=30 // Fanout_Default (Default Rule)
FanoutControl Fanout_SOIC [All] p0 off: scope1count=1 scope1_0_kind=Board scope1_0_value=Board scope2count=1 scope2_0_kind=Board scope2_0_value=Board commentlength=71 // Protel DXP Scope 1 Expression Was: IsSOIC   Fanout_SOIC (Default Rule)
FanoutControl Fanout_BGA [All] p0 off: scope1count=1 scope1_0_kind=Board scope1_0_value=Board scope2count=1 scope2_0_kind=Board scope2_0_value=Board commentlength=69 // Protel DXP Scope 1 Expression Was: IsBGA   Fanout_BGA (Default Rule)
FanoutControl Fanout_LCC [All] p0 off: scope1count=1 scope1_0_kind=Board scope1_0_value=Board scope2count=1 scope2_0_kind=Board scope2_0_value=Board commentlength=69 // Protel DXP Scope 1 Expression Was: IsLCC   Fanout_LCC (Default Rule)
FanoutControl Fanout_LCC [IsLCC] p1: bgadir=Out bgaviamode=Centered fanoutstyle=Auto fanoutdirection=Alternating viagrid=1 // Fanout_LCC (Default Rule)
FanoutControl Fanout_BGA [IsBGA] p2: bgadir=Out bgaviamode=Centered fanoutstyle=Auto fanoutdirection=Alternating viagrid=1 // Fanout_BGA (Default Rule)
FanoutControl Fanout_Default [All] p4: bgadir=Out bgaviamode=Centered fanoutstyle=Auto fanoutdirection=Alternating viagrid=1 // Fanout_Default (Default Rule)
FanoutControl Fanout_Small [(CompPinCount < 5)] p5: bgadir=Out bgaviamode=Centered fanoutstyle=Auto fanoutdirection=OutThenIn viagrid=1 // Fanout_Small (Default Rule)
Height [All] p0: scope1count=1 scope1_0_kind=Board scope1_0_value=Board scope2count=1 scope2_0_kind=Board scope2_0_value=Board commentlength=0
HoleSize [All] p0: scope1count=1 scope1_0_kind=Board scope1_0_value=Board scope2count=1 scope2_0_kind=Board scope2_0_value=Board commentlength=0 absolutevalues=TRUE maxlimit=251 minlimit=5.9 maxpercent=80.000 minpercent=20.000
HoleSize [All] p1: absolutevalues=TRUE maxlimit=251 minlimit=5.9 maxpercent=80.000 minpercent=20.000
HoleToHoleClearance [All] p0 off: scope1count=1 scope1_0_kind=Board scope1_0_value=Board scope2count=1 scope2_0_kind=Board scope2_0_value=Board commentlength=78 // Protel DXP Scope 1 Expression Was: All and  (not InPadClass('Non Plated'))
HoleToHoleClearance [All and  (not InPadClass('Non Plated'))] p1: gap=10 allowstackedmicrovias=TRUE
LayerPairs [All] p0: scope1count=1 scope1_0_kind=Board scope1_0_value=Board scope2count=1 scope2_0_kind=Board scope2_0_value=Board commentlength=0 enforce=TRUE
MatchedLengths U13-J2 [All] p0 off: scope1count=1 scope1_0_kind=Board scope1_0_value=Board scope2count=1 scope2_0_kind=Board scope2_0_value=Board commentlength=63 tolerance=400 amplitude=200 gap=20 style=90-Degree // Protel DXP Scope 1 Expression Was: InxSignalClass('U13-J2')
MatchedLengths U13-U8 [All] p0 off: scope1count=1 scope1_0_kind=Board scope1_0_value=Board scope2count=1 scope2_0_kind=Board scope2_0_value=Board commentlength=63 tolerance=400 amplitude=200 gap=20 style=90-Degree // Protel DXP Scope 1 Expression Was: InxSignalClass('U13-U8')
MatchedLengths U13-J11 [All] p0 off: scope1count=1 scope1_0_kind=Board scope1_0_value=Board scope2count=1 scope2_0_kind=Board scope2_0_value=Board commentlength=64 tolerance=400 amplitude=200 gap=20 style=90-Degree // Protel DXP Scope 1 Expression Was: InxSignalClass('U13-J11')
MatchedLengths [All] p0: scope1count=1 scope1_0_kind=NetClass scope1_0_value=LVDS_IC scope2count=1 scope2_0_kind=Board scope2_0_value=Board commentlength=0 tolerance=20 amplitude=200 gap=20 style=90-Degree
MatchedLengths USB [All] p0 off: scope1count=1 scope1_0_kind=Board scope1_0_value=Board scope2count=1 scope2_0_kind=Board scope2_0_value=Board commentlength=60 tolerance=5 amplitude=200 gap=20 style=90-Degree // Protel DXP Scope 1 Expression Was: InxSignalClass('USB')
MatchedLengths JTAG [All] p0 off: scope1count=1 scope1_0_kind=Board scope1_0_value=Board scope2count=1 scope2_0_kind=Board scope2_0_value=Board commentlength=61 tolerance=100 amplitude=200 gap=20 style=90-Degree // Protel DXP Scope 1 Expression Was: InxSignalClass('JTAG')
MatchedLengths SPI [All] p0 off: scope1count=1 scope1_0_kind=Board scope1_0_value=Board scope2count=1 scope2_0_kind=Board scope2_0_value=Board commentlength=70 tolerance=200 amplitude=200 gap=20 style=90-Degree // Protel DXP Scope 1 Expression Was: InxSignalClass('SPI & HOSTINT')
MatchedLengths QSPI [All] p0 off: scope1count=1 scope1_0_kind=Board scope1_0_value=Board scope2count=1 scope2_0_kind=Board scope2_0_value=Board commentlength=61 tolerance=100 amplitude=200 gap=20 style=90-Degree // Protel DXP Scope 1 Expression Was: InxSignalClass('QSPI')
MatchedLengths U13-J11 [InxSignalClass('U13-J11')] p1: tolerance=400 checknetsindiffpair=FALSE checkdiffpairvsdiffpair=TRUE checkxsignals=TRUE checkothers=TRUE
MatchedLengths U13-J2 [InxSignalClass('U13-J2')] p2: tolerance=400 checknetsindiffpair=FALSE checkdiffpairvsdiffpair=TRUE checkxsignals=TRUE checkothers=TRUE
MatchedLengths U13-U8 [InxSignalClass('U13-U8')] p3: tolerance=400 checknetsindiffpair=FALSE checkdiffpairvsdiffpair=TRUE checkxsignals=TRUE checkothers=TRUE
MatchedLengths [InNetClass('LVDS_IC')] p4: tolerance=20 checknetsindiffpair=FALSE checkdiffpairvsdiffpair=TRUE checkxsignals=TRUE checkothers=TRUE
MatchedLengths USB [InxSignalClass('USB')] p5: tolerance=5 checknetsindiffpair=TRUE checkdiffpairvsdiffpair=FALSE checkxsignals=FALSE checkothers=FALSE
MatchedLengths QSPI [InxSignalClass('QSPI')] p6: tolerance=100 checknetsindiffpair=FALSE checkdiffpairvsdiffpair=TRUE checkxsignals=TRUE checkothers=TRUE
MatchedLengths SPI [InxSignalClass('SPI & HOSTINT')] p7: tolerance=200 checknetsindiffpair=FALSE checkdiffpairvsdiffpair=TRUE checkxsignals=TRUE checkothers=TRUE
MatchedLengths JTAG [InxSignalClass('JTAG')] p8: tolerance=100 checknetsindiffpair=FALSE checkdiffpairvsdiffpair=TRUE checkxsignals=TRUE checkothers=TRUE
MinimumAnnularRing [All] p0: scope1count=1 scope1_0_kind=Board scope1_0_value=Board scope2count=1 scope2_0_kind=Board scope2_0_value=Board commentlength=0 minimumring=3
MinimumAnnularRing MinimumAnnularRing_ThermalPadVias [All] p0 off: scope1count=1 scope1_0_kind=Board scope1_0_value=Board scope2count=1 scope2_0_kind=Board scope2_0_value=Board commentlength=63 minimumring=3 // Protel DXP Scope 1 Expression Was: IsVia and InAnyComponent
MinimumAnnularRing MinimumAnnularRing_ThermalPadVias [IsVia and InAnyComponent] p1: minimumring=3
MinimumAnnularRing [All] p2: minimumring=3
MinimumSolderMaskSliver [All] p0: scope1count=1 scope1_0_kind=Board scope1_0_value=Board scope2count=1 scope2_0_kind=Board scope2_0_value=Board commentlength=0
MinimumSolderMaskSliver [All] p1: minsoldermaskwidth=2.9
NetAntennae [All] p0: scope1count=1 scope1_0_kind=Board scope1_0_value=Board scope2count=1 scope2_0_kind=Board scope2_0_value=Board commentlength=0
PasteMaskExpansion [All] p0: scope1count=1 scope1_0_kind=Board scope1_0_value=Board scope2count=1 scope2_0_kind=Board scope2_0_value=Board commentlength=0 expansion=0
PlaneClearance [All] p0: scope1count=1 scope1_0_kind=Board scope1_0_value=Board scope2count=1 scope2_0_kind=Board scope2_0_value=Board commentlength=0 clearance=20
PlaneConnect [All] p0: scope1count=1 scope1_0_kind=Board scope1_0_value=Board scope2count=1 scope2_0_kind=Board scope2_0_value=Board commentlength=0 planeconnectstyle=Direct reliefexpansion=10 reliefentries=4 reliefconductorwidth=10 reliefairgap=10
PlaneConnect [All] p1: planeconnectstyle=Direct reliefexpansion=10 reliefentries=4 reliefconductorwidth=10 reliefairgap=10
PolygonConnect [All] p0: scope1count=1 scope1_0_kind=Board scope1_0_value=Board scope2count=1 scope2_0_kind=Board scope2_0_value=Board commentlength=0 connectstyle=Direct reliefconductorwidth=10 reliefentries=4 polygonreliefangle="90 Angle"
PolygonConnect [All] p1: connectstyle=Direct reliefconductorwidth=10 reliefentries=4 polygonreliefangle="90 Angle" airgapwidth=10
RoomDefinition PROC106B_Hardware [All] p0 off: scope1count=1 scope1_0_kind=ComponentClass scope1_0_value=PROC106B_Hardware scope2count=1 scope2_0_kind=Board scope2_0_value=Board commentlength=0 region_x1=44324542 region_y1=53246462 region_x2=50581612 region_y2=59382522 confinementstyle=ConfineIn
RoomDefinition PROC106B_Hardware [InComponentClass('PROC106B_Hardware')] p1 off: confinementstyle=ConfineIn formatcopy=TRUE lockcomponents=FALSE outline 3741.3,4404.25 4366.16,4404.25 4366.16,3790.65 3740.45,3790.65
RoutingCorners [All] p0: scope1count=1 scope1_0_kind=Board scope1_0_value=Board scope2count=1 scope2_0_kind=Board scope2_0_value=Board commentlength=0 cornerstyle=45-Degree minsetback=100 maxsetback=100
RoutingLayers [All] p0: scope1count=1 scope1_0_kind=Board scope1_0_value=Board scope2count=1 scope2_0_kind=Board scope2_0_value=Board commentlength=0 top layer=Automatic mid layer 1=Automatic mid layer 2=Automatic mid layer 3=Automatic mid layer 6=Automatic mid layer 7=Automatic mid layer 8=Automatic bottom layer=Automatic
RoutingPriority [All] p0: scope1count=1 scope1_0_kind=Board scope1_0_value=Board scope2count=1 scope2_0_kind=Board scope2_0_value=Board commentlength=0
RoutingTopology [All] p0: scope1count=1 scope1_0_kind=Board scope1_0_value=Board scope2count=1 scope2_0_kind=Board scope2_0_value=Board commentlength=0 topology=Shortest
RoutingVias [All] p0: scope1count=1 scope1_0_kind=Board scope1_0_value=Board scope2count=1 scope2_0_kind=Board scope2_0_value=Board commentlength=0 holewidth=8 width=18 viastyle="Through Hole" minholewidth=7.87 minwidth=17 maxholewidth=40 maxwidth=30
RoutingVias ThermalPadVias [All] p0 off: scope1count=1 scope1_0_kind=Board scope1_0_value=Board scope2count=1 scope2_0_kind=Board scope2_0_value=Board commentlength=63 holewidth=7.87 width=19.68 viastyle="Through Hole" minholewidth=7.87 minwidth=19.68 maxholewidth=12.99 maxwidth=23.62 // Protel DXP Scope 1 Expression Was: IsVia and InAnyComponent
RoutingVias [All] p1: holewidth=8 width=18 viastyle="Through Hole" minholewidth=7.87 minwidth=17 maxholewidth=40 maxwidth=30
RoutingVias ThermalPadVias [IsVia and InAnyComponent] p2: holewidth=7.87 width=19.68 viastyle="Through Hole" minholewidth=7.87 minwidth=19.68 maxholewidth=12.99 maxwidth=23.62
ShortCircuit [All] p0: scope1count=1 scope1_0_kind=Board scope1_0_value=Board scope2count=1 scope2_0_kind=Board scope2_0_value=Board commentlength=0 allowed=FALSE
SilkToBoardRegionClearance [All] p0 off: scope1count=1 scope1_0_kind=Board scope1_0_value=Board scope2count=1 scope2_0_kind=Board scope2_0_value=Board commentlength=130 // Protel DXP Scope 1 Expression Was: Not ((IsComment or IsDesignator) And (Hide <> 'False')) and not InRegion(1000,500,4000,800)
SilkToBoardRegionClearance [Not ((IsComment or IsDesignator) And (Hide <> 'False')) and not InRegion(1000,500,4000,800)] p1:
SilkToSilkClearance [All] p0: scope1count=1 scope1_0_kind=Board scope1_0_value=Board scope2count=1 scope2_0_kind=Board scope2_0_value=Board commentlength=0
SilkToSilkClearance [All] p1: silktosilkclearance=3
SilkToSolderMaskClearance "Silk to Solder Mask Opening" [All] p0: scope1count=1 scope1_0_kind=Board scope1_0_value=Board scope2count=1 scope2_0_kind=Board scope2_0_value=Board commentlength=0
SilkToSolderMaskClearance SilkToComponentPadClearance [All] p0 off: scope1count=1 scope1_0_kind=Board scope1_0_value=Board scope2count=1 scope2_0_kind=Board scope2_0_value=Board commentlength=87 // Protel DXP Scope 1 Expression Was: (IsPad or IsFill or IsRegion) and InAnycomponent
SilkToSolderMaskClearance SilkToComponentPadClearance [(IsPad or IsFill or IsRegion) and InAnycomponent] p1: minsilkscreentomaskgap=2 clearancetoexposedcopper=TRUE
SilkToSolderMaskClearance "Silk to Solder Mask Opening" [All] p2: minsilkscreentomaskgap=2 clearancetoexposedcopper=FALSE
SolderMaskExpansion [All] p0: scope1count=1 scope1_0_kind=Board scope1_0_value=Board scope2count=1 scope2_0_kind=Board scope2_0_value=Board commentlength=0 expansion=1.97
SolderMaskExpansion [All] p1: expansion=1.97
UnRoutedNet [All] p0: scope1count=1 scope1_0_kind=Board scope1_0_value=Board scope2count=1 scope2_0_kind=Board scope2_0_value=Board commentlength=0
UnpouredPolygon [All] p0: scope1count=1 scope1_0_kind=Board scope1_0_value=Board scope2count=1 scope2_0_kind=Board scope2_0_value=Board commentlength=0
Width RF [All] p0: scope1count=1 scope1_0_kind=NetClass scope1_0_value=RF scope2count=1 scope2_0_kind=Board scope2_0_value=Board commentlength=0 maxlimit=100 minlimit=5.5 preferedwidth=10
Width [All] p0: scope1count=1 scope1_0_kind=Board scope1_0_value=Board scope2count=1 scope2_0_kind=Board scope2_0_value=Board commentlength=0 maxlimit=100 minlimit=4 preferedwidth=6
Width RF [InNetClass('RF')] p1: maxlimit=100 minlimit=5.5 preferedwidth=10 toplayer_prefwidth=12 midlayer1_minwidth=10 midlayer1_maxwidth=10 midlayer2_minwidth=10 midlayer2_maxwidth=10 midlayer3_minwidth=10 midlayer3_maxwidth=10 midlayer6_minwidth=10 midlayer6_maxwidth=10 midlayer7_minwidth=10 midlayer7_maxwidth=10 midlayer8_minwidth=10 midlayer8_maxwidth=10 bottomlayer_minwidth=10 bottomlayer_maxwidth=10 minimp=50.000000 maximp=50.000000 favimp=50.000000
Width [All] p2: maxlimit=100 minlimit=4 preferedwidth=6 toplayer_maxwidth=40 toplayer_prefwidth=6.7 midlayer1_minwidth=4.2 midlayer1_maxwidth=20 midlayer1_prefwidth=4.2 midlayer2_minwidth=4.5 midlayer2_maxwidth=15 midlayer2_prefwidth=5.95 midlayer7_minwidth=4.5 midlayer7_maxwidth=15 midlayer7_prefwidth=5.95 midlayer8_minwidth=6 midlayer8_prefwidth=10 bottomlayer_maxwidth=40 bottomlayer_prefwidth=6.7 minimp=50.000000 maximp=50.000000 favimp=50.000000
14 further rules are at their usual default settings.

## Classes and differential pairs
pad class "Non Plated": Designator1_2- Designator7_1- Designator22_1- Designator23- FL2-1 FL2-2 FL3-1 FL3-2 FL12-1 FL12-2 FL22-1 FL22-2 Free-
net class PWR: AR_1P0_RF1 AR_1P0_RF2 AR_1P2 AR_1V4_APLL AR_1V4_SYNTH AR_1V8 PMIC_1V0 PMIC_1V2 PMIC_1V8
net class 100E: AR_LVDS_0_N AR_LVDS_0_P AR_LVDS_1_N AR_LVDS_1_P AR_LVDS_CLK_N AR_LVDS_CLK_P AR_LVDS_FRCLK_N AR_LVDS_FRCLK_P
net class RF: NetA1_4 NetC22_1 NetC41_1 NetC93_1 NetC93_2 RF_N RF_P
component class PROC106B_RST_GPIOs_I2C: C6 C9 C10 C11 C12 C13 C38 C39 C72 C120 C125 J3 LD2 LD3 LD5 Q1 R13 R18 R38 R42 R51 R57 R67 R68 R69 R70 R71 R72 R73 R77 R78 R80 R81 R82 R93 R96 R97 R98 R107 R108 R111 R124 R125 R129 R177 R178 SW2 SW3 TP15 TP20 U5 U6 U7 U16 Y4
component class PROC106B_PMIC: C30 C31 C32 C33 C34 C44 C45 C46 C47 C48 C49 C50 C51 C52 C53 C54 C73 C75 C76 C77 C111 C112 C113 C121 C124 C131 L2 L3 L4 L5 L11 L12 L13 L14 LD1 R25 R26 R28 R31 R32 R33 R34 R35 R36 R37 R39 R50 R52 R53 R54 R55 R56 TP5 TP12 U1
component class PROC106B_HD_CONN_PWR_SW: C127 C128 C129 FL22 J2 J11 L16 R10 R11 R12 R14 R20 R24 R27 R29 R58 R88 R92 R130 R132 R133 R135 R137 R138 R140 R142 R143 R144 R145 R146 R147 R148 R149 R150 R151 R152 R153 R154 R155 R157 R186 R187 R188 R189 R190 RA1 RA2 RA3 RA4 RA5 RA6 RA7 RA8 RA9 TP10 TP13 U19
component class PROC106B_FLASH_USB_TO_UART: C1 C2 C3 C4 C100 C101 C126 D1 FL2 J1 LD4 R6 R15 R19 R40 R41 R43 R44 R45 R46 R47 R48 R49 R60 R61 R62 R63 R64 R65 TP18 TP19 TP26 U3 U9 U18
component class PROC106B_CAN_INTERFACE: C40 C43 C105 C106 C107 C108 C109 C110 FL3 FL12 J8 J10 R66 R74 R104 R105 R106 R114 R115 R116 R117 R118 R119 R120 R121 R122 R123 R126 R127 R128 R134 R136 R139 R141 U11 U12 U13 U17
component class PROC106B_BT_DISPLAY: A1 C5 C7 C8 C15 C16 C17 C18 C19 C20 C21 C22 C23 C24 C25 C26 C27 C28 C29 C35 C36 C37 C41 C86 C93 C99 C104 C114 C115 C116 C117 C118 C119 J4 J6 J7 L1 L6 L7 L8 L9 L10 LD6 R17 R30 R76 R79 R86 R87 R89 R90 R91 R94 R95 R99 R100 R101 R102 R110 R112 R113 R131 R160 R161 R166 R168 R180 R181 R182 R183 R184 R185 TP16 TP27 TP46 U4 U8 U10 U14 Y2 Y3
component class PROC106B_AOP_PWR: C55 C56 C57 C58 C59 C60 C61 C62 C63 C64 C65 C66 C67 C68 C69 C70 C74 C78 C79 C80 C81 C82 C83 C84 C85 C87 C88 C89 C90 C91 C92 C94 C95 C96 C97 C98 C102 C103 TP11
component class PROC106B_AOP_IO: C14 C71 C130 R2 R3 R4 R5 R7 R8 R9 R21 R22 R23 R59 R75 R83 R84 R85 R103 R158 R159 R170 R171 R172 R174 R176 S3 TP2 TP3 TP6 TP7 TP8 TP9 TP14 TP17 U2 Y1
component class PROC106B_ANALOG_MUX: C42 C122 C123 J5 L15 R1 R16 S1 S2 TP4 U15
component class PROC106B_Hardware: FID1 FID2 FID3 FID4 FID5 FID6 ZZ1 ZZ2 ZZ3 ZZ4 ZZ5.1 ZZ5.2
component class FiducialMark: Designator1_2 Designator7_1 Designator22_1 Designator23 FID1 FID2 FID3 FID4 FID5 FID6
component class AssemblyNote: ZZ1 ZZ2 ZZ3 ZZ4 ZZ5.1 ZZ5.2
differential pair NewDifferentialPair3: +X48M_P -X48M_N
differential pair AR_LVDS_CLK_J: +NetJ2_36 -NetJ2_34
differential pair AR_LVDS_1_J: +NetJ2_42 -NetJ2_40
differential pair AR_LVDS_0_J: +NetJ2_48 -NetJ2_46
differential pair USB_R: +NetR60_1 -NetR41_1
differential pair NewDifferentialPair1: +NetJ8_1 -NetJ8_3
differential pair USB: +USB_DP -USB_DM
differential pair NewDifferentialPair2: +NetJ10_1 -NetJ10_3
differential pair AR_LVDS_CLK: +AR_LVDS_CLK_P -AR_LVDS_CLK_N
differential pair AR_LVDS_FRCLK: +AR_LVDS_FRCLK_P -AR_LVDS_FRCLK_N
differential pair AR_LVDS_1: +AR_LVDS_1_P -AR_LVDS_1_N
differential pair AR_LVDS_0: +AR_LVDS_0_P -AR_LVDS_0_N
differential pair AR_LVDS_0_R: +NetJ11_56 -NetJ11_58
differential pair AR_LVDS_1_R: +NetJ11_50 -NetJ11_52
differential pair AR_LVDS_CLK_R: +NetJ11_44 -NetJ11_46
differential pair " ": +NetJ11_26 -NetJ11_28

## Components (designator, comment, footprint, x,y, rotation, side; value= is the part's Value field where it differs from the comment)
A1 "ANT016008LCS2442MA2" FP-ANT016008LCS2442MA2_SMT_ANT-0 7284.33,4589.83 r180 top
C1 "GCM21BR71A106KE22L" 0805L 3004.01,3914.32 r270 top
C2 "GCM155R71C104KA55D" 0402L 3005.89,4400.66 r180 bottom
C3 "GCM155R71C104KA55D" 0402L 3005.89,4400.66 r180 top
C4 "GCM21BR71A106KE22L" 0805L 3004.01,3914.26 r90 bottom
C5 "CL03A105MO3NRNH" FP-CL03A105MO3NRNH_0201-IPC_C 6882.81,3977 r180 bottom
C6 "GRM033R6YA104KE14D" "FP-GRM033R6YA104KE14D_0201 (0603 Metric)-IPC_C" 5234.38,4538.7 r90 bottom
C7 "CL05A106MP5NUNC" 0402_070 6844.78,3720.79 r0 bottom
C8 "CL03A103KA3NNNC" FP-CL03A103KA3NNNC_0201-IPC_C 6903.19,3719.01 r180 bottom
C9 "GRM033R6YA104KE14D" "FP-GRM033R6YA104KE14D_0201 (0603 Metric)-IPC_C" 5197.1,3791.56 r90 bottom locked
C10 "GRM033R6YA104KE14D" "FP-GRM033R6YA104KE14D_0201 (0603 Metric)-IPC_C" 5162.69,3875.17 r90 bottom
C11 "CL03A105MO3NRNH" FP-CL03A105MO3NRNH_0201-IPC_C 5172.1,3791.41 r270 bottom
C12 "GRM033R6YA104KE14D" "FP-GRM033R6YA104KE14D_0201 (0603 Metric)-IPC_C" 5580.92,3737.11 r0 bottom
C13 "GRM033R6YA104KE14D" "FP-GRM033R6YA104KE14D_0201 (0603 Metric)-IPC_C" 5242.93,4010.48 r0 bottom
C14 "CGA1A2C0G1H4R7C030BA" FP-CGA1A2C0G1H4R7C030BA_0201-IPC_C 4153.98,3817.27 r180 top
C15 "CL03A105MO3NRNH" FP-CL03A105MO3NRNH_0201-IPC_C 4750.21,4143.82 r270 top
C16 "CL03A105MO3NRNH" FP-CL03A105MO3NRNH_0201-IPC_C 4713.47,4143.92 r270 top
C17 "GRM0335C1H8R0BA01D" "FP-GRM0335C1H8R0BA01D_0201 (0603 metric)-IPC_C" 6613.33,4250.88 r0 top
C18 "GRM0335C1H8R0BA01D" "FP-GRM0335C1H8R0BA01D_0201 (0603 metric)-IPC_C" 6634.87,4127.04 r180 top
C19 "250R05L120JV4T" FP-250R05L120JV4T_0201-IPC_C 6277.6,4370.87 r270 top
C20 "250R05L120JV4T" FP-250R05L120JV4T_0201-IPC_C 6277.6,4324.98 r90 top
C21 "CL05C120JB5NNNC" 0402L 6540.73,4344.09 r270 top
C22 "GCM1555C1H1R0CA16D" 0402L 6468.51,4395.47 r270 top
C23 "GCM1555C1H1R0CA16D" 0402L 6395.4,4324.42 r180 top
C24 "CL03A105MO3NRNH" FP-CL03A105MO3NRNH_0201-IPC_C 6142.33,4003.46 r180 top
C25 "GRM033R6YA104KE14D" "FP-GRM033R6YA104KE14D_0201 (0603 Metric)-IPC_C" 6157.34,4271.39 r180 top
C26 "GRM033R6YA104KE14D" "FP-GRM033R6YA104KE14D_0201 (0603 Metric)-IPC_C" 6142.18,4042.21 r180 top
C27 "GRM033R6YA104KE14D" "FP-GRM033R6YA104KE14D_0201 (0603 Metric)-IPC_C" 6518.42,4103.16 r270 top
C28 "CL05A226MQ5N6J8" 0402S 6458.05,3903.24 r0 top
C29 "CL05A226MQ5N6J8" 0402S 6471.97,4137.37 r180 bottom
C30 "GCM155R71C224KE02D" 0402L 3295.87,4189 r90 top
C31 "CGA2B2C0G1H391J050BA" 0402L 3667.5,4538.34 r180 top
C32 "CGA2B2C0G1H391J050BA" 0402L 3200.34,4518.49 r0 top
C33 "CGA2B2C0G1H391J050BA" 0402L 3615.39,4098.42 r270 top
C34 "CGA2B2C0G1H391J050BA" 0402L 3231.35,3936.68 r270 top
C35 "GRM033R6YA104KE14D" "FP-GRM033R6YA104KE14D_0201 (0603 Metric)-IPC_C" 6534.66,4138.22 r0 top
C36 "GRM033R6YA104KE14D" "FP-GRM033R6YA104KE14D_0201 (0603 Metric)-IPC_C" 6516.27,4239.23 r90 top
C37 "GRM033R6YA104KE14D" "FP-GRM033R6YA104KE14D_0201 (0603 Metric)-IPC_C" 6287.19,4411.08 r180 top
C38 "250R05L120JV4T" FP-250R05L120JV4T_0201-IPC_C 5245.41,3795.56 r180 bottom
C39 "250R05L120JV4T" FP-250R05L120JV4T_0201-IPC_C 5291.16,3795.56 r0 bottom
C40 "GRM033R6YA104KE14D" "FP-GRM033R6YA104KE14D_0201 (0603 Metric)-IPC_C" 6581.1,4040.29 r180 top
C41 "GCM1555C1H1R0CA16D" 0402L 6461.93,4540.91 r0 top
C42 "CL05A106MP5NUNC" 0402_070 6821.81,4040 r90 top
C43 "GRM033R6YA104KE14D" "FP-GRM033R6YA104KE14D_0201 (0603 Metric)-IPC_C" 5891.78,4292.07 r0 top
C44 "CGA4J1X7T0J226M125AC" FP-CGA4J1X7T0J226M125AC_0805-MFG 3516.1,4538.33 r0 top
C45 "CGA4J1X7T0J226M125AC" FP-CGA4J1X7T0J226M125AC_0805-MFG 3336.18,4538.34 r180 top
C46 "CGA4J1X7T0J226M125AC" FP-CGA4J1X7T0J226M125AC_0805-MFG 3514.81,3840.95 r0 top
C47 "CGA4J1X7T0J226M125AC" FP-CGA4J1X7T0J226M125AC_0805-MFG 3335.76,3832.63 r180 top
C48 "CGA4J1X7T0J226M125AC" FP-CGA4J1X7T0J226M125AC_0805-MFG 3335.76,3750.6 r180 top
C49 "CGA4J1X7T0J226M125AC" FP-CGA4J1X7T0J226M125AC_0805-MFG 3514.81,3770.11 r0 top
C50 "GCM21BR71A106KE22L" 0805_HV1 3355.89,4015.14 r0 top
C51 "GCM21BR71A106KE22L" 0805_HV1 3495.89,4015.14 r180 top
C52 "GCM21BR71A106KE22L" 0805_HV1 3357.86,4352.35 r0 top
C53 "GCM21BR71A106KE22L" 0805_HV1 3495.89,4352.35 r180 top
C54 "CGA4J1X7T0J226M125AC" FP-CGA4J1X7T0J226M125AC_0805-MFG 3514.81,3699.04 r0 top
C55 "GCM21BR71A106KE22L" 0805L 3908.19,4239.7 r0 bottom
C56 "GCM155R71C224KE02D" 0402L 4323.95,4419.07 r0 bottom
C57 "GCM155R71C224KE02D" 0402L 3686.18,4257.19 r180 top
C58 "GCM155R71C224KE02D" 0402L 3686.18,4218.19 r180 top
C59 "GCM21BR71A106KE22L" 0805L 3700.56,4275.26 r90 bottom
C60 "GCM155R71C224KE02D" 0402L 4309.75,4188.46 r90 bottom
C61 "GCM155R71C224KE02D" 0402L 4018.33,4342.22 r270 bottom
C62 "GCM21BR71A106KE22L" 0805L 4040,3970.52 r90 bottom
C63 "GCM155R71C224KE02D" 0402L 3935.07,3856.83 r180 bottom
C64 "GCM155R71C224KE02D" 0402L 3967.69,3945.83 r180 bottom
C65 "GCM21BR71A106KE22L" 0805L 3674.97,3943.67 r180 bottom
C66 "GCM155R71C224KE02D" 0402L 3865.49,3945.78 r90 bottom
C67 "GCM155R71C224KE02D" 0402L 3790.94,3955.68 r0 bottom
C68 "GCM155R71C224KE02D" 0402L 3713.57,3943.79 r90 top
C69 "CGA2B3X7R1H473K050BB" 0402L 3822.75,3862.61 r180 bottom
C70 "GCM21BR71A106KE22L" 0805L 3908.19,4023.7 r0 bottom
C71 "CGA1A2C0G1H4R7C030BA" FP-CGA1A2C0G1H4R7C030BA_0201-IPC_C 4106.98,3817.45 r180 top
C72 "GRM033R6YA104KE14D" "FP-GRM033R6YA104KE14D_0201 (0603 Metric)-IPC_C" 4845,4415.28 r0 top
C73 "CGA4J1X7T0J226M125AC" FP-CGA4J1X7T0J226M125AC_0805-MFG 3299.16,3669 r180 top
C74 "GCM188R70J225KE22D" 0603L 3687.18,4009.15 r180 top
C75 "CGA4J1X7T0J226M125AC" FP-CGA4J1X7T0J226M125AC_0805-MFG 3702.01,3803.74 r0 bottom
C76 "GCM21BR71A106KE22L" 0805L 3427.48,4623.45 r0 bottom
C77 "CGA4J1X7T0J226M125AC" FP-CGA4J1X7T0J226M125AC_0805-MFG 3136,4614 r0 top
C78 "GCM21BR71A106KE22L" 0805L 3908.19,4167.7 r0 bottom
C79 "GCM188R70J225KE22D" 0603L 3710.6,4167.45 r90 bottom
C80 "GCM155R71C224KE02D" 0402L 3686.2,4141.13 r180 top
C81 "GCM155R71C224KE02D" 0402L 3686.2,4177.66 r180 top
C82 "GCM21BR71A106KE22L" 0805L 3908.19,4095.7 r0 bottom
C83 "GCM188R70J225KE22D" 0603L 3655.22,4120.08 r90 bottom
C84 "GCM155R71C224KE02D" 0402L 3687.73,4060.46 r180 top
C85 "GCM155R71C224KE02D" 0402L 3687.73,4097.51 r180 top
C86 "GRM033R6YA104KE14D" "FP-GRM033R6YA104KE14D_0201 (0603 Metric)-IPC_C" 6410.84,3907.91 r270 top
C87 "GCM155R71C224KE02D" 0402L 4314.32,4094.43 r270 bottom
C88 "GCM155R71C224KE02D" 0402L 4085.98,4438.9 r90 bottom
C89 "GCM188R71C105KA64D" 0603L 4132.97,3811.96 r0 bottom
C90 "GCM188R71C105KA64D" 0603L 4028.67,3857.43 r180 bottom
C91 "GCM155R71C104KA55D" 0402L 4218.02,4377.65 r90 bottom
C92 "GCM155R71C104KA55D" 0402L 4352.69,4188.46 r270 bottom
C93 "CL05C120JB5NNNC" 0402L 6586.38,4589.83 r180 top
C94 "GCM155R71C224KE02D" 0402L 4364,3874.31 r270 bottom
C95 "GCM155R71C224KE02D" 0402L 4376.53,3958.4 r270 bottom
C96 "GCM155R71C224KE02D" 0402L 4094.31,4356.14 r270 bottom
C97 "GCM155R71C224KE02D" 0402L 4188.97,3908.47 r90 bottom
C98 "GCM155R71C224KE02D" 0402L 3918.65,4396.76 r0 bottom
C99 "GJM1555C1H1R8BB01D" 0402L 7156.66,4589.69 r180 top
C100 "GCM188R71C105KA64D" 0603L 3220.18,4028.4 r90 top
C101 "GCM155R71C104KA55D" 0402L 3257.08,4075.84 r270 bottom
C102 "GCM188R70J225KE22D" 0603L 4367.44,4062.4 r270 bottom
C103 "GCM188R70J225KE22D" 0603L 4150.97,4365.07 r270 bottom
C104 "GJM1555C1H1R8BB01D" 0402L 7217.64,4570.15 r270 top
C105 "GRM033R6YA104KE14D" "FP-GRM033R6YA104KE14D_0201 (0603 Metric)-IPC_C" 6003.64,4429.32 r90 top
C106 "GRM155R71H472KA01D" 0402L 6042.33,4472.32 r90 top
C107 "GRM033R6YA104KE14D" "FP-GRM033R6YA104KE14D_0201 (0603 Metric)-IPC_C" 6735.03,4433.22 r90 top
C108 "GRM033R6YA104KE14D" "FP-GRM033R6YA104KE14D_0201 (0603 Metric)-IPC_C" 6709.78,3866.01 r270 top
C109 "GRM033R6YA104KE14D" "FP-GRM033R6YA104KE14D_0201 (0603 Metric)-IPC_C" 6877.41,3768.9 r0 top
C110 "GRM155R71H472KA01D" 0402L 6951.81,3773.61 r90 top
C111 "CGA4J1X7T0J226M125AC" FP-CGA4J1X7T0J226M125AC_0805-MFG 3639.35,3729.75 r180 bottom
C112 "GCM21BR71A106KE22L" 0805L 3109.68,3663.43 r180 top
C113 "GCM21BR71A106KE22L" 0805L 3638.2,3839.06 r90 top
C114 "GRM033R6YA104KE14D" "FP-GRM033R6YA104KE14D_0201 (0603 Metric)-IPC_C" 6174.57,3747.34 r180 bottom
C115 "CL03A105MO3NRNH" FP-CL03A105MO3NRNH_0201-IPC_C 5764.72,3872.2 r0 top
C116 "CL03A105MO3NRNH" FP-CL03A105MO3NRNH_0201-IPC_C 5764.72,3843.74 r0 top
C117 "GRM033R6YA104KE14D" "FP-GRM033R6YA104KE14D_0201 (0603 Metric)-IPC_C" 6050.15,3984.72 r90 top
C118 "GRM033R6YA104KE14D" "FP-GRM033R6YA104KE14D_0201 (0603 Metric)-IPC_C" 6272.5,3733.87 r270 bottom
C119 "GRM033R6YA104KE14D" "FP-GRM033R6YA104KE14D_0201 (0603 Metric)-IPC_C" 6304.91,3909.21 r90 bottom
C120 "GRM033R6YA104KE14D" "FP-GRM033R6YA104KE14D_0201 (0603 Metric)-IPC_C" 4905.18,4369.7 r0 top
C121 "GCM21BR71A106KE22L" 0805L 3541.25,3686.2 r270 bottom
C122 "CL05A106MP5NUNC" 0402_070 6771.81,4040 r270 top
C123 "GRM033R6YA104KE14D" "FP-GRM033R6YA104KE14D_0201 (0603 Metric)-IPC_C" 5580.17,4531.94 r270 top
C124 "CGA4J1X7T0J226M125AC" FP-CGA4J1X7T0J226M125AC_0805-MFG 3702.01,3871.27 r0 bottom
